(* Logix 5000 project; controller SIKO_example_SN5oEIP_RSL5K_V20 vendor 1 type 14 code 107 rev 20.19; software revision 20.04 *)

TASK MainTask (continuous, watchdog 500 ms) : MainProgram

MODULES
   Local : vendor 1 type 14 code 107 (Compact 0, rev 20.19)
      ABC : ETHERNET-MODULE (Ethernet 10.129.140.221, rev 1.1, Output RPI 10 ms)
END_MODULES

ADD_ON_INSTRUCTION SIKO_AG05_CSW_POS   (* revision 1.0, vendor SIKO GmbH *)
// Control-/Status-Word
VAR_IN_OUT
   DC_Com : SIKO_SN5_COM; {required}
END_VAR
VAR_INPUT
   bc00_Off1 : BOOL; {visible}   // Bit = 1 (Required for movement)
   bc01_Off2 : BOOL; {visible}   // Bit = 1 (Required for movement)
   bc02_Off3 : BOOL; {visible}   // Bit = 1 (Required for movement)
   bc03_IntermediateStop : BOOL; {visible}
   bc04_StartTravelJob : BOOL; {visible}
   bc05_AckError : BOOL; {visible}
   bc06_InchingMode1 : BOOL; {visible}
   bc07_Inching2Pos : BOOL; {visible}
   bc08_Inching2Neg : BOOL; {visible}
   bc09_KeyEnable : BOOL; {visible}
   bcCal : BOOL; {visible}
END_VAR
VAR_OUTPUT
   bs00_Supply : BOOL; {access Read Only, visible}
   bs01_ReadinessToTravel : BOOL; {access Read Only, visible}
   bs02_UpperLimit : BOOL; {access Read Only, visible}
   bs03_LowerLimit : BOOL; {access Read Only, visible}
   bs04_ActuatorTravels : BOOL; {access Read Only, visible}
   bs05_InPos : BOOL; {access Read Only, visible}
   bs06_ActiveTravelJob : BOOL; {access Read Only, visible}
   bs07_Error : BOOL; {access Read Only, visible}
   bs08_OperationEnabled : BOOL; {access Read Only, visible}
   bs09_SwitchLock : BOOL; {access Read Only, visible}
   bs10_TravelJobAck : BOOL; {access Read Only, visible}
   bs11_BatteryWarning : BOOL; {access Read Only, visible}
   bs12_CurrentLimiting : BOOL; {access Read Only, visible}
   bsCalExec : BOOL; {access Read Only, visible}
END_VAR

ROUTINE Logic   (* structured text *)
   ////////////////////////////////////////////////////////////////////////
   // Version history
   ////////////////////////////////////////////////////////////////////////
   // Date       | Vers. | created              | Author          | Remark
   // dd.mm.yyyy |       | with                 |                 |
   // --------------------------------------------------------------------
   // 10.10.2018 | 0.01  | RSLogix5000 V 19.01  | SIKO GmbH / MK  | alpha
   ////////////////////////////////////////////////////////////////////////
   //
   ///////////////////////////////////////////////////////////////////////////////////////////////
   // Control-/ Statusword symbolic
   //
   DC_Com.bc00 	:= bc00_Off1;
   DC_Com.bc01 	:= bc01_Off2;
   DC_Com.bc02 	:= bc02_Off3;
   DC_Com.bc03 	:= bc03_IntermediateStop;
   DC_Com.bc04 	:= bc04_StartTravelJob;
   DC_Com.bc05 	:= bc05_AckError;
   DC_Com.bc06 	:= bc06_InchingMode1;
   DC_Com.bc07 	:= bc07_Inching2Pos;
   DC_Com.bc08 	:= bc08_Inching2Neg;
   DC_Com.bc09 	:= bc09_KeyEnable;
   DC_Com.bc10 	:= 0;
   DC_Com.bc11 	:= 0;
   DC_Com.bc12 	:= 0;
   DC_Com.bc13 	:= 0;
   DC_Com.bc14 	:= 0;
   DC_Com.bc15 	:= 0;
   DC_Com.bcCal 	:= bcCal;
   
   bs00_Supply 			:= DC_Com.bs00;
   bs01_ReadinessToTravel 	:= DC_Com.bs01;
   bs02_UpperLimit 		:= DC_Com.bs02;
   bs03_LowerLimit 		:= DC_Com.bs03;
   bs04_ActuatorTravels 	:= DC_Com.bs04;
   bs05_InPos 				:= DC_Com.bs05;
   bs06_ActiveTravelJob 	:= DC_Com.bs06;
   bs07_Error				:= DC_Com.bs07;
   bs08_OperationEnabled 	:= DC_Com.bs08;
   bs09_SwitchLock 		:= DC_Com.bs09;
   bs10_TravelJobAck 		:= DC_Com.bs10;
   bs11_BatteryWarning 	:= DC_Com.bs11;
   bs12_CurrentLimiting	:= DC_Com.bs12;
   bsCalExec 				:= DC_Com.bsCalExec;
   
   
   
   
   
   
   
END_ROUTINE
END_ADD_ON_INSTRUCTION

ADD_ON_INSTRUCTION SIKO_AP10   (* revision 5.0 4, vendor SIKO GmbH *)
// SIKO PositionLine AP10 AOI
// Revision note:
// Usable with AP10 Firmware Vers. >= 1.06
VAR_IN_OUT
   DC_OutputBuffer : SINT[10]; {required}
   DC_AbcOutputRegister : AB:ETHERNET_MODULE_SINT_314Bytes:O:0; {required}
END_VAR
VAR_INPUT
   DC_AbcStartByteOut : INT; {required}
END_VAR
VAR_IN_OUT
   DC_InputBuffer : SINT[10]; {required}
   DC_AbcInputRegister : AB:ETHERNET_MODULE_SINT_314Bytes:I:0; {required}
END_VAR
VAR_INPUT
   DC_AbcStartByteIn : INT; {required}
   nNodeId : SINT; {visible}   // Temporaray Node_address
   nSetValue : DINT; {visible}
END_VAR
VAR_OUTPUT
   nActualValue : DINT; {access Read Only, visible}
END_VAR
VAR_INPUT
   nParameterAdrRead1 : SINT; {visible}
   nParameterAdrRead2 : SINT; {visible}
   nParameterAdrRead3 : SINT; {visible}
   bcStartRead : BOOL; {visible}
   bcStartWrite : BOOL; {visible}
   bcStartCopy : BOOL; {visible}
   bcResetCounterActivity : BOOL; {visible}
END_VAR
VAR_OUTPUT
   nCounterRead : INT; {access Read Only, visible}
   nCounterWrite : INT; {access Read Only, visible}
   nCounterCopy : INT; {access Read Only, visible}
   nErrorCode1 : SINT; {access Read Only, visible}
   nErrorCode2 : SINT; {access Read Only, visible}
   p00_NodeAddress_r : SINT; {access Read Only, visible}   // Parmeter: 0x00
END_VAR
VAR_INPUT
   p00_NodeAddress_w : SINT := 31; {visible}   // Parmeter: 0x00
END_VAR
VAR_OUTPUT
   p01_Baudrate_r : SINT; {access Read Only}   // Parmeter: 0x01
END_VAR
VAR_INPUT
   p01_Baudrate_w : SINT := 1;   // Parmeter: 0x01
END_VAR
VAR_OUTPUT
   p02_BusTimeout_r : SINT; {access Read Only}   // Parmeter: 0x02
END_VAR
VAR_INPUT
   p02_BusTimeout_w : SINT := 20;   // Parmeter: 0x02
END_VAR
VAR_OUTPUT
   p03_ReplyWriteSetPoint_r : SINT;   // Parmeter: 0x03
END_VAR
VAR_INPUT
   p03_ReplyWriteSetPoint_w : SINT; {access Read Only}   // Parmeter: 0x03
END_VAR
VAR_OUTPUT
   p04_EnableKeysTime_r : SINT; {access Read Only}   // Parmeter: 0x04
END_VAR
VAR_INPUT
   p04_EnableKeysTime_w : SINT := 5;   // Parmeter: 0x04
END_VAR
VAR_OUTPUT
   p05_KeyFunctionEnable1Calibrate_r : SINT; {access Read Only}   // Parmeter: 0x05
END_VAR
VAR_INPUT
   p05_KeyFunctionEnable1Calibrate_w : SINT := 1;   // Parmeter: 0x05
END_VAR
VAR_OUTPUT
   p06_LedFlashing_r : SINT; {access Read Only}   // Parmeter: 0x06
END_VAR
VAR_INPUT
   p06_LedFlashing_w : SINT;   // Parmeter: 0x06
END_VAR
VAR_OUTPUT
   p07_Led3Green_r : SINT; {access Read Only}   // Parmeter: 0x07
END_VAR
VAR_INPUT
   p07_Led3Green_w : SINT := 1;   // Parmeter: 0x07
END_VAR
VAR_OUTPUT
   p08_Led2Red_r : SINT; {access Read Only}   // Parmeter: 0x08
END_VAR
VAR_INPUT
   p08_Led2Red_w : SINT := 1;   // Parmeter: 0x08
END_VAR
VAR_OUTPUT
   p09_Led1Green_r : SINT; {access Read Only}   // Parmeter: 0x09
END_VAR
VAR_INPUT
   p09_Led1Green_w : SINT := 1;   // Parmeter: 0x09
END_VAR
VAR_OUTPUT
   p0A_DecimalPlaces_r : SINT; {access Read Only}   // Parmeter: 0x0A
END_VAR
VAR_INPUT
   p0A_DecimalPlaces_w : SINT;   // Parmeter: 0x0A
END_VAR
VAR_OUTPUT
   p0B_DisplayDivisor_r : SINT; {access Read Only}   // Parmeter: 0x0B
END_VAR
VAR_INPUT
   p0B_DisplayDivisor_w : SINT;   // Parmeter: 0x0B
END_VAR
VAR_OUTPUT
   p0C_DirectionIndication_r : SINT; {access Read Only}   // Parmeter: 0x0C
END_VAR
VAR_INPUT
   p0C_DirectionIndication_w : SINT := 1;   // Parmeter: 0x0C
END_VAR
VAR_OUTPUT
   p0D_DisplayOrientation_r : SINT; {access Read Only}   // Parmeter: 0x0D
END_VAR
VAR_INPUT
   p0D_DisplayOrientation_w : SINT;   // Parmeter: 0x0D
END_VAR
VAR_OUTPUT
   p0E_ProgrammingMode_r : SINT; {access Read Only}   // Parmeter: 0x0E
END_VAR
VAR_INPUT
   p0E_ProgrammingMode_w : SINT; {access Read Only}   // Parmeter: 0x0E
END_VAR
VAR_OUTPUT
   p1B_CountingDirection_r : SINT; {access Read Only}   // Parmeter: 0x1B
END_VAR
VAR_INPUT
   p1B_CountingDirection_w : SINT;   // Parmeter: 0x1B
END_VAR
VAR_OUTPUT
   p1C_ResolutionPerRevolution_r : DINT; {access Read Only}   // Parmeter: 0x1C
END_VAR
VAR_INPUT
   p1C_ResolutionPerRevolution_w : DINT := 880;   // Parmeter: 0x1C
END_VAR
VAR_OUTPUT
   p1E_Offset_r : INT; {access Read Only}   // Parmeter: 0x1E
END_VAR
VAR_INPUT
   p1E_Offset_w : INT;   // Parmeter: 0x1E
END_VAR
VAR_OUTPUT
   p1F_CalibrationValue_r : DINT; {access Read Only}   // Parmeter: 0x1F
END_VAR
VAR_INPUT
   p1F_CalibrationValue_w : DINT;   // Parmeter: 0x1F
END_VAR
VAR_OUTPUT
   p20_TargetWindow1_r : INT; {access Read Only}   // Parmeter: 0x20
END_VAR
VAR_INPUT
   p20_TargetWindow1_w : INT;   // Parmeter: 0x20
END_VAR
VAR_OUTPUT
   p21_PosType_r : SINT; {access Read Only}   // Parmeter: 0x21
END_VAR
VAR_INPUT
   p21_PosType_w : SINT;   // Parmeter: 0x21
END_VAR
VAR_OUTPUT
   p22_LoopLength_r : INT; {access Read Only}   // Parmeter: 0x22
END_VAR
VAR_INPUT
   p22_LoopLength_w : INT;   // Parmeter: 0x22
END_VAR
VAR_OUTPUT
   p28_OperatingMode_r : SINT; {access Read Only}   // Parmeter: 0x28
END_VAR
VAR_INPUT
   p28_OperatingMode_w : SINT;   // Parmeter: 0x28
END_VAR
VAR_OUTPUT
   p30_Display2Line_r : SINT; {access Read Only}   // Parmeter: 0x30
END_VAR
VAR_INPUT
   p30_Display2Line_w : SINT := 1;   // Parmeter: 0x30
END_VAR
VAR_OUTPUT
   p31_TargetWindow2_r : INT; {access Read Only}   // Parmeter: 0x31
END_VAR
VAR_INPUT
   p31_TargetWindow2_w : INT;   // Parmeter: 0x31
   p32_PosWindow2Visual_w : SINT;   // Parmeter: 0x32
END_VAR
VAR_OUTPUT
   p32_PosWindow2Visual_r : SINT; {access Read Only}   // Parmeter: 0x32
   p33_DisplayDivisorUse_r : SINT; {access Read Only}   // Parmeter: 0x33
END_VAR
VAR_INPUT
   p33_DisplayDivisorUse_w : SINT;   // Parmeter: 0x33
   p34_DifferenceValueCalc_w : SINT;   // Parmeter: 0x34
END_VAR
VAR_OUTPUT
   p34_DifferenceValueCalc_r : SINT; {access Read Only}   // Parmeter: 0x34
   p35_KeyFunctionEnable2IncrMeas_r : SINT; {access Read Only}   // Parmeter: 0x35
END_VAR
VAR_INPUT
   p35_KeyFunctionEnable2IncrMeas_w : SINT := 1;   // Parmeter: 0x35
END_VAR
VAR_OUTPUT
   p39_Led4Red_r : SINT; {access Read Only}   // Parmeter: 0x39
END_VAR
VAR_INPUT
   p39_Led4Red_w : SINT := 1;   // Parmeter: 0x39
END_VAR
VAR_OUTPUT
   p3A_LcdBacklightFlashing_r : SINT; {access Read Only}   // Parmeter: 0x3A
END_VAR
VAR_INPUT
   p3A_LcdBacklightFlashing_w : SINT;   // Parmeter: 0x3A
END_VAR
VAR_OUTPUT
   p3B_LcdBacklightWhite_r : SINT; {access Read Only}   // Parmeter: 0x3B
END_VAR
VAR_INPUT
   p3B_LcdBacklightWhite_w : SINT := 1;   // Parmeter: 0x3B
END_VAR
VAR_OUTPUT
   p3C_LcdBacklightRed_r : SINT; {access Read Only}   // Parmeter: 0x3C
END_VAR
VAR_INPUT
   p3C_LcdBacklightRed_w : SINT := 1;   // Parmeter: 0x3C
END_VAR
VAR_OUTPUT
   p3D_KeyFunctionEnable3Config_r : SINT; {access Read Only}   // Parmeter: 0x3D
END_VAR
VAR_INPUT
   p3D_KeyFunctionEnable3Config_w : SINT := 1;   // Parmeter: 0x3D
END_VAR
VAR_OUTPUT
   p3E_AcknowledgementSettings_r : SINT; {access Read Only}   // Parmeter: 0x3E
END_VAR
VAR_INPUT
   p3E_AcknowledgementSettings_w : SINT;   // Parmeter: 0x3E
END_VAR
VAR_OUTPUT
   p3F_IndicationFactor_r : SINT; {access Read Only}   // Parmeter: 0x3F
END_VAR
VAR_INPUT
   p3F_IndicationFactor_w : SINT;   // Parmeter: 0x3F
END_VAR
VAR_OUTPUT
   p63_VoltageBattery_r : INT; {access Read Only}   // Parmeter: 0x63
   p65_DeviceCode_r : INT; {access Read Only}   // Parmeter: 0x65
   p67_SoftwareVersion_r : INT; {access Read Only}   // Parmeter: 0x67
   p80_NumberOfErrorsRecorded_r : SINT; {access Read Only}   // Parmeter: 0x80
   p81_Error01_r : SINT; {access Read Only}   // Parmeter: 0x81
   p82_Error02_r : SINT; {access Read Only}   // Parmeter: 0x82
   p83_Error03_r : SINT; {access Read Only}   // Parmeter: 0x83
   p84_Error04_r : SINT; {access Read Only}   // Parmeter: 0x84
   p85_Error05_r : SINT; {access Read Only}   // Parmeter: 0x85
   p86_Error06_r : SINT; {access Read Only}   // Parmeter: 0x86
   p87_Error07_r : SINT; {access Read Only}   // Parmeter: 0x87
   p88_Error08_r : SINT; {access Read Only}   // Parmeter: 0x88
   p89_Error09_r : SINT; {access Read Only}   // Parmeter: 0x89
   p8A_Error10_r : SINT; {access Read Only}   // Parmeter: 0x8A
   p96_InputErrors_r : INT; {access Read Only}   // Parmeter: 0x96
END_VAR
VAR_INPUT
   pA0_SystemCommand_w : SINT;   // Parmeter: 0xA0
   pA7_ExecuteCalibration_w : SINT;   // Parmeter: 0xA7
END_VAR
VAR_OUTPUT
   pA8_ProgrammingModeOnOff_r : SINT; {access Read Only}   // Parmeter: 0xA8
END_VAR
VAR_INPUT
   pA8_ProgrammingModeOnOff_w : SINT;   // Parmeter: 0xA8
   pAA_FreezeAV_w : SINT;   // Parmeter: 0xAA
END_VAR
VAR_OUTPUT
   pC5_AdcValuesSensor_r : DINT;   // Parmeter: 0xC5
   pCF_PeriodCounter_r : DINT;   // Parmeter: 0xCF
   pD0_ResponseDelay_r : SINT; {access Read Only}   // Parmeter: 0xD0
END_VAR
VAR_INPUT
   pD0_ResponseDelay_w : SINT;   // Parmeter: 0xD0
   pD2_AutoIdAssignment_w : SINT;   // Parmeter: 0xD2
END_VAR
VAR_OUTPUT
   pFA_SystemStatusword_r : INT; {access Read Only}   // Parmeter: 0xFA
   pFB_SetPoint1_r : DINT; {access Read Only}   // Parmeter: 0xFB
END_VAR
VAR_INPUT
   pFB_SetPoint1_w : DINT;   // Parmeter: 0xFB
END_VAR
VAR_OUTPUT
   pFC_DifferentialValue_r : DINT; {access Read Only}   // Parmeter: 0xFC
   pFE_ActualPosition_r : DINT; {access Read Only}   // Parmeter: 0xFE
   pFF_SetPoint2_r : DINT; {access Read Only}   // Parmeter: 0xFF
END_VAR
VAR_INPUT
   pFF_SetPoint2_w : DINT;   // Parmeter: 0xFF
   bc02_ValidityOfSetpoint1 : BOOL;
   bc03_DisplayRange : BOOL;
   bc04_AcknowledgmentTargetWindow1Static : BOOL;
   bc05_ErrorAcknowledgment : BOOL;
   bc06_AcknowledgementOfSetpoint2 : BOOL;
   bc07_DataIdentifier : BOOL;
   bc09_ValidityOfSetpoint2 : BOOL;
   bc10_AcknowledgementOfSetpoint1 : BOOL;
   bc11_Led1GreenLeft : BOOL;
   bc12_Led3GreenRight : BOOL;
   bc13_Led4RedRight : BOOL;
   bc14_Led2RedLeft : BOOL;
   bc15_LedBlinking : BOOL;
END_VAR
VAR_OUTPUT
   bs00_DirectionIndicationCw : BOOL; {access Read Only}
   bs01_DirectionIndicationCcw : BOOL; {access Read Only}
   bs02_ValiditySetpoint1 : BOOL; {access Read Only}
   bs03_TargetWindow2Dynamic : BOOL; {access Read Only}
   bs04_TargetWindow1Static : BOOL; {access Read Only}
   bs05_TargetWindow1Dynamic : BOOL; {access Read Only}
   bs06_Deviation : BOOL; {access Read Only}
   bs07_DeviceError : BOOL; {access Read Only}
   bs08_OutputOfPositionValue : BOOL; {access Read Only}
   bs09_PositionValueIncrementalMeasurement : BOOL; {access Read Only}
   bs10_ValiditySetpoint2 : BOOL;
   bs11_BatteryStatus : BOOL; {access Read Only}
   bs12_SensorError : BOOL;
   bs13_ButtonLeft : BOOL; {access Read Only}
   bs14_ButtonStar : BOOL; {access Read Only}
   bs15_ButtonUp : BOOL; {access Read Only}
   bsDone : BOOL; {access Read Only, visible}
   bsBusy : BOOL; {access Read Only, visible}
   bsGeneralError : BOOL; {access Read Only, visible}
   bsFaultDataRecive : BOOL; {access Read Only, visible}
END_VAR
VAR
   vnTrigger : SINT; {access None}
   vnCounterToggle : SINT; {access None}
   vnParameterAdrReceive : INT; {access None}
   vnParameterAdrSend : INT; {access None}
   vnParameterDataReceive : DINT; {access None}
   vnParameterDataSend : DINT; {access None}
   vbRefresh : BOOL; {access None}
   vbOsrWrite : BOOL; {access None}
   vbOsrRead : BOOL; {access None}
   vnOutputDataOffset : DINT := -200; {access None}
   vnDcOutputBufferTemp : DINT; {access None}
   vnDcInputBufferTemp : DINT; {access None}
   vbOsrCopy : BOOL; {access None}
END_VAR

ROUTINE Logic   (* structured text *)
   ///////////////////////////////////////////////////////////////////////////////////////////////
   // Name:	SIKO_AP10
   ///////////////////////////////////////////////////////////////////////////////////////////////
   // Version history
   ///////////////////////////////////////////////////////////////////////////////////////////////
   // Date        | Version  | created under          	| Author    		| Remark
   // dd.mm.yyyy  | 		  |							|					|
   // -----------------------------------------------------------------------------------
   // 26.05.2015  | 4.9.0    | V19.01.00 (CPR 9 SR 3)  | SIKO GmbH / SC 	| basic version
   // 07.09.2015  | 5.0.1    | V19.01.00 (CPR 9 SR 3)  | SIKO GmbH / SC 	| Release Candidate
   ///////////////////////////////////////////////////////////////////////////////////////////////
   
   ///////////////////////////////////////////////////////////////////////////////////////////////
   // read inputs synchonous
   //
   CPS(DC_AbcInputRegister.data[DC_AbcStartByteIn] , DC_InputBuffer[0],10); // read from ABC
   
   ///////////////////////////////////////////////////////////////////////////////////////////////
   // input byte swop to parameter data and format transfer vnParameterAdrReceive
   //
   cop (DC_InputBuffer[5], vnDcInputBufferTemp, 1);					//Data Type Conversion
   swpb (vnDcInputBufferTemp, Reverse, vnParameterDataReceive);
   
   vnParameterAdrReceive := 16#00ff and DC_InputBuffer[2];
   
   ///////////////////////////////////////////////////////////////////////////////////////////////
   // Telegram acknowledge checked for bad reply
   //
   if vnParameterAdrReceive = 253
   then
   	bsFaultDataRecive := 1;
   	nErrorCode1 := DC_InputBuffer[8];
   	nErrorCode2 := DC_InputBuffer[7];
   
   else
   	bsFaultDataRecive := 0;
   	nErrorCode1 := 0;
   	nErrorCode2 := 0;
   end_if;
   
   
   ///////////////////////////////////////////////////////////////////////////////////////////////
   // Request (Read/Write) successful
   //
   if DC_OutputBuffer[2] = DC_InputBuffer[2] and not bsFaultDataRecive
   then
   	if nCounterRead <> 0
   	then
   		nCounterRead := nCounterRead + 1;
   	end_if;
   	if nCounterWrite <> 0
   	then
   		nCounterWrite := nCounterWrite + 1;
   	end_if;
   end_if;
   
   ///////////////////////////////////////////////////////////////////////////////////////////////
   // Control word
   //
   DC_OutputBuffer[4].0 := 0;
   DC_OutputBuffer[4].1 := 0;
   DC_OutputBuffer[4].2 := bc02_ValidityOfSetpoint1;                // Validity of setpoint1; 0=invalid; 1=valid
   DC_OutputBuffer[4].3 := bc03_DisplayRange;                       // Display range full
   DC_OutputBuffer[4].4 := bc04_AcknowledgmentTargetWindow1Static;  // Acknowledgment target window1 static
   DC_OutputBuffer[4].5 := bc05_ErrorAcknowledgment;                // Acknowledged
   DC_OutputBuffer[4].6 := bc06_AcknowledgementOfSetpoint2;         // Acknowledgment Set Value2
   DC_OutputBuffer[4].7 := bc07_DataIdentifier;                     // Data format, Number / ASCII-String
   DC_OutputBuffer[3].0 := 0;
   DC_OutputBuffer[3].1 := bc09_ValidityOfSetpoint2;                // Validity of setpoint2
   DC_OutputBuffer[3].2 := bc10_AcknowledgementOfSetpoint1;         // Acknowledgment Set Value2
   DC_OutputBuffer[3].3 := bc11_Led1GreenLeft;                      // LED1 green left
   DC_OutputBuffer[3].4 := bc12_Led3GreenRight;                     // LED3 green right
   DC_OutputBuffer[3].5 := bc13_Led4RedRight;                       // LED4 red right
   DC_OutputBuffer[3].6 := bc14_Led2RedLeft;                        // LED2 red left
   DC_OutputBuffer[3].7 := bc15_LedBlinking;                        // LED blinking
   
   ///////////////////////////////////////////////////////////////////////////////////////////////
   // Start Read
   //
   IF bcStartRead AND (nCounterRead = 0) AND (nCounterWrite = 0) AND (nCounterCopy = 0) AND NOT vbOsrRead
   THEN
   	nCounterRead := 1;
   	nCounterWrite := 0;
   	nCounterCopy := 0;
   	vbOsrRead := 1;
   END_IF;
   IF NOT bcStartRead and vbOsrRead
   THEN
   	vbOsrRead := 0;
   END_IF;
   
   ///////////////////////////////////////////////////////////////////////////////////////////////
   // Start Write
   //
   IF bcStartWrite AND (nCounterRead = 0) AND (nCounterWrite = 0) AND (nCounterCopy = 0) AND NOT vbOsrWrite
   THEN
   	nCounterWrite := 1;
   	nCounterRead := 0;
   	nCounterCopy := 0;
   	vbOsrWrite := 1;
   END_IF;
   IF NOT bcStartWrite and vbOsrWrite
   THEN
   	vbOsrWrite := 0;
   END_IF;
   
   ///////////////////////////////////////////////////////////////////////////////////////////////
   // copy read to write parameters
   //
   IF bcStartCopy AND (nCounterRead = 0) AND (nCounterWrite = 0) AND (nCounterCopy = 0) AND NOT vbOsrCopy
   THEN
   	nCounterCopy := 1;
   	nCounterWrite := 0;
   	nCounterRead := 0;
   	vbOsrCopy := 1;
   END_IF;
   IF NOT bcStartCopy and vbOsrCopy
   THEN
   	vbOsrCopy := 0;
   END_IF;
   
   ///////////////////////////////////////////////////////////////////////////////////////////////
   // reset counter (nCounter...) and activity (bcStart...)
   //
   IF bcResetCounterActivity
   THEN
   	bcStartRead :=0;
   	bcStartWrite :=0;
   	bcStartCopy :=0;
   	nCounterCopy := 0;
   	nCounterWrite := 0;
   	nCounterRead := 0;
   	vnCounterToggle := 0;
   	bcResetCounterActivity := 0;
   END_IF;
   
   ///////////////////////////////////////////////////////////////////////////////////////////////
   // Parameter request
   //
   if nCounterRead > 0
   	then
   	DC_OutputBuffer[0] := 0;
   	vnParameterDataSend := 0;
   	CASE nCounterRead OF
   	1: //0x00 Note address
   	    vnParameterAdrSend := 0;
   	2: //0x01 Baud rate
   		vnParameterAdrSend := 1;
   	3: //0x02 Bus Timeout
         	vnParameterAdrSend := 2;
   	4: //0x03 Response parameter to a setpoint write access
         	vnParameterAdrSend := 3;
   	5: //0x04 Keys enable time: Configuration start delay
         	vnParameterAdrSend := 4;
   	6: //0x05 Key function enable1: Calibration enable
         	vnParameterAdrSend := 5;
   	7: //0x06 LED flashing
         	vnParameterAdrSend := 6;
   	8: //0x07 LED3 (green right)
         	vnParameterAdrSend := 7;
   	9: //0x08 LED2 (red left)
         	vnParameterAdrSend := 8;
   	10: //0x09 LED1 (green left)
         	vnParameterAdrSend := 9;
   	11: //0x0A Decimal places
         	vnParameterAdrSend := 10;
   	12: //0x0B Display divisor (ADI)
         	vnParameterAdrSend := 11;
   	13: //0x0C Direction indicators (CW, CCW)
         	vnParameterAdrSend := 12;
   	14: //0x0D Display orientation
         	vnParameterAdrSend := 13;
   	15: //0x0E Configuration programming mode
         	vnParameterAdrSend := 14;
   	16: //0x1B Counting direction
         	vnParameterAdrSend := 27;
   	17: //0x1C Resolution per revolution
         	vnParameterAdrSend := 28;
   	18: //0x1E Offset value
         	vnParameterAdrSend := 30;
   	19: //0x1F Calibration value
         	vnParameterAdrSend := 31;
   	20: //0x20 Target window1 (near field)
         	vnParameterAdrSend := 32;
   	21: //0x21 Positioning type (loop type)
         	vnParameterAdrSend := 33;
   	22: //0x22 Loop length
         	vnParameterAdrSend := 34;
   	23: //0x28 Operating mode
         	vnParameterAdrSend := 40;
   	24: //0x30 Display in the 2nd row
         	vnParameterAdrSend := 48;
   	25: //0x31 Target window2 (extended)
         	vnParameterAdrSend := 49;
   	26: //0x32 Target window2 visualization
         	vnParameterAdrSend := 50;
   	27: //0x33 Application of the display divisor (ADI application)
         	vnParameterAdrSend := 51;
   	28: //0x34 Formation of the differential value
         	vnParameterAdrSend := 52;
   	29: //0x35 Key function enable2: Incremental measurement enable
         	vnParameterAdrSend := 53;
   	30: //0x39 LED4 (red right)
         	vnParameterAdrSend := 57;
   	31: //0x3A LCD backlight flashing
         	vnParameterAdrSend := 58;
   	32: //0x3B LCD backlight white
         	vnParameterAdrSend := 59;
   	33: //0x3C LCD backlight red
         	vnParameterAdrSend := 60;
   	34: //0x3D Key function enable3: Configuration enable via keyboard
         	vnParameterAdrSend := 61;
   	35: //0x3E Acknowledgement settings
         	vnParameterAdrSend := 62;
   	36: //0x3F Indication factor
   		//vnParameterAdrSend := 63;
   	37: //0x63 Battery voltage
         	vnParameterAdrSend := 99;
   	38: //0x65 Device identification
         	vnParameterAdrSend := 101;
   	39: //0x67 Software version
         	vnParameterAdrSend := 103;
   	40: //0x80 Number of errors
         	vnParameterAdrSend := 128;
   	41: //0x81 Error 01
         	vnParameterAdrSend := 129;
   	42: //0x82 Error 02
         	vnParameterAdrSend := 130;
   	43: //0x83 Error 03
         	vnParameterAdrSend := 131;
   	44: //0x84 Error 04
         	vnParameterAdrSend := 132;
   	45: //0x85 Error 05
         	vnParameterAdrSend := 133;
   	46: //0x86 Error 06
         	vnParameterAdrSend := 134;
   	47: //0x87 Error 07
         	vnParameterAdrSend := 135;
   	48: //0x88 Error 08
         	vnParameterAdrSend := 136;
   	49: //0x89 Error 09
         	vnParameterAdrSend := 137;
   	50: //0x8A Error 10
         	vnParameterAdrSend := 138;
   	51: //0x96 Input Errors
   		//vnParameterAdrSend := 150;
   	52: //0xC5 ADC values of the sensor
         	vnParameterAdrSend := 197;
   	53: //0xCF Period counter
         	vnParameterAdrSend := 207;
   	54: //0xD0 Response delay
         	vnParameterAdrSend := 208;
   	55: //0xFA System Status word
         	vnParameterAdrSend := 250;
   	56: //0xFB Setpoint1
         	vnParameterAdrSend := 251;
   	57: //0xFC Differential value
         	vnParameterAdrSend := 252;
   	58: //0xFE Position value
         	vnParameterAdrSend := 254;
   	59: //0xFF Setpoint2
         	vnParameterAdrSend := 255;
   	60: // Parameter anforderung abgeschlossen
   		nCounterRead := 0;
     	END_CASE;
   end_if;
   
   ///////////////////////////////////////////////////////////////////////////////////////////////
   // Parameter Settings
   //
   if nCounterWrite > 0
   	then
   	DC_OutputBuffer[0] := 1;
   	CASE nCounterWrite OF
   	1: //Programming mode
   		IF pA8_ProgrammingModeOnOff_w >= 0 and pA8_ProgrammingModeOnOff_w <= 1
   		THEN
   	      	vnParameterAdrSend := 168;
   			vnParameterDataSend:= pA8_ProgrammingModeOnOff_w;
   		END_IF;
   	2: //Note address
   		IF p00_NodeAddress_w <> p00_NodeAddress_r or bsFaultDataRecive
   		THEN
   	      	vnParameterAdrSend := 0;
   			vnParameterDataSend:= p00_NodeAddress_w;
   		END_IF;
   	3: //Baudrate
   		IF p01_Baudrate_w <> p01_Baudrate_r or bsFaultDataRecive
   		THEN
   	      	vnParameterAdrSend := 1;
   			vnParameterDataSend:= p01_Baudrate_w;
   		END_IF;
   	4: //Bus Timeout
   		IF p02_BusTimeout_w <> p02_BusTimeout_r or bsFaultDataRecive
   		THEN
   	      	vnParameterAdrSend := 2;
   			vnParameterDataSend:= p02_BusTimeout_w;
   		END_IF;
   	5: //Response parameter to a setpoint write access
   		IF p03_ReplyWriteSetPoint_w <> p03_ReplyWriteSetPoint_r or bsFaultDataRecive
   		THEN
   	      	vnParameterAdrSend := 3;
   			vnParameterDataSend:= p03_ReplyWriteSetPoint_w;
   		END_IF;
   	6: ///Keys enable time: Configuration start delay
   		IF p04_EnableKeysTime_w <> p04_EnableKeysTime_r or bsFaultDataRecive
   		THEN
   	      	vnParameterAdrSend := 4;
   			vnParameterDataSend:= p04_EnableKeysTime_w;
   		END_IF;
   	7: //Key function enable1: Calibration enable
   		IF p05_KeyFunctionEnable1Calibrate_w <> p05_KeyFunctionEnable1Calibrate_r or bsFaultDataRecive
   		THEN
   	      	vnParameterAdrSend := 5;
   			vnParameterDataSend:= p05_KeyFunctionEnable1Calibrate_w;
   		END_IF;
   	8: //LED flashing
   		IF p06_LedFlashing_w <> p06_LedFlashing_r or bsFaultDataRecive
   		THEN
   	      	vnParameterAdrSend := 6;
   			vnParameterDataSend:= p06_LedFlashing_w;
   		END_IF;
   	9: //LED3 (green right)
   		IF p07_Led3Green_w <> p07_Led3Green_r or bsFaultDataRecive
   		THEN
   	      	vnParameterAdrSend := 7;
   			vnParameterDataSend:= p07_Led3Green_w;
   		END_IF;
   	10: //LED2 (red left)
   		IF p08_Led2Red_w <> p08_Led2Red_r or bsFaultDataRecive
   		THEN
   	      	vnParameterAdrSend := 8;
   			vnParameterDataSend:= p08_Led2Red_w;
   		END_IF;
   	11: //LED1 (green left)
   		IF p09_Led1Green_w <> p09_Led1Green_r or bsFaultDataRecive
   		THEN
   	      	vnParameterAdrSend := 9;
   			vnParameterDataSend:= p09_Led1Green_w;
   		END_IF;
   	12: //Decimal places
   		IF p0A_DecimalPlaces_w <> p0A_DecimalPlaces_r or bsFaultDataRecive
   		THEN
   	      	vnParameterAdrSend := 10;
   			vnParameterDataSend := p0A_DecimalPlaces_w;
   		END_IF;
   	13: //Display divisor (ADI)
   		IF p0B_DisplayDivisor_w <> p0B_DisplayDivisor_r or bsFaultDataRecive
   		THEN
   	      	vnParameterAdrSend := 11;
   			vnParameterDataSend:= p0B_DisplayDivisor_w;
   		END_IF;
   	14: //Direction indicators (CW, CCW)
   		IF p0C_DirectionIndication_w <> p0C_DirectionIndication_r or bsFaultDataRecive
   		THEN
   	      	vnParameterAdrSend := 12;
   			vnParameterDataSend:= p0C_DirectionIndication_w;
   		END_IF;
   	15: //Display orientation
   		IF p0D_DisplayOrientation_w <> p0D_DisplayOrientation_r or bsFaultDataRecive
   		THEN
   	      	vnParameterAdrSend := 13;
   			vnParameterDataSend:= p0D_DisplayOrientation_w;
   		END_IF;
   	16: //Configuration programming mode
   		IF p0E_ProgrammingMode_w <> p0E_ProgrammingMode_r or bsFaultDataRecive
   		THEN
   	      	vnParameterAdrSend := 14;
   			vnParameterDataSend:= p0E_ProgrammingMode_w;
   		END_IF;
   	17: //Counting direction
   		IF p1B_CountingDirection_w <> p1B_CountingDirection_r or bsFaultDataRecive
   		THEN
   	      	vnParameterAdrSend := 27;
   			vnParameterDataSend:= p1B_CountingDirection_w;
   		END_IF;
   	18: //Resolution per revolution
   		IF p1C_ResolutionPerRevolution_w <> p1C_ResolutionPerRevolution_r or bsFaultDataRecive
   		THEN
   	      	vnParameterAdrSend := 28;
   			vnParameterDataSend:= p1C_ResolutionPerRevolution_w;
   		END_IF;
   	19: //Offset value
   		IF p1E_Offset_w <> p1E_Offset_r or bsFaultDataRecive
   		THEN
   	      	vnParameterAdrSend := 30;
   			vnParameterDataSend:= p1E_Offset_w;
   		END_IF;
   	20: //Calibration value
   		IF p1F_CalibrationValue_w <> p1F_CalibrationValue_r or bsFaultDataRecive
   		THEN
   	      	vnParameterAdrSend := 31;
   			vnParameterDataSend:= p1F_CalibrationValue_w;
   		END_IF;
   	21: //Target window1 (near field)
   		IF p20_TargetWindow1_w <> p20_TargetWindow1_r or bsFaultDataRecive
   		THEN
   	      	vnParameterAdrSend := 32;
   			vnParameterDataSend:= p20_TargetWindow1_w;
   		END_IF;
   	22: //Positioning type (loop type)
   		IF p21_PosType_w <> p21_PosType_r or bsFaultDataRecive
   		THEN
   	      	vnParameterAdrSend := 33;
   			vnParameterDataSend:= p21_PosType_w;
   		END_IF;
   	23: //Loop length
   		IF p22_LoopLength_w <> p22_LoopLength_r or bsFaultDataRecive
   		THEN
   	      	vnParameterAdrSend := 34;
   			vnParameterDataSend:= p22_LoopLength_w;
   		END_IF;
   	24: //Operating mode
   		IF p28_OperatingMode_w <> p28_OperatingMode_r or bsFaultDataRecive
   		THEN
   	      	vnParameterAdrSend := 40;
   			vnParameterDataSend:= p28_OperatingMode_w;
   		END_IF;
   	25: //Display in the 2nd row
   		IF p30_Display2Line_w <> p30_Display2Line_r or bsFaultDataRecive
   		THEN
   	      	vnParameterAdrSend := 48;
   			vnParameterDataSend:= p30_Display2Line_w;
   		END_IF;
   	26: //Target window2 (extended)
   		IF p31_TargetWindow2_w <> p31_TargetWindow2_r or bsFaultDataRecive
   		THEN
   	      	vnParameterAdrSend := 49;
   			vnParameterDataSend:= p31_TargetWindow2_w;
   		END_IF;
   	27: //Target window2 visualization
   		IF p32_PosWindow2Visual_w <> p32_PosWindow2Visual_r or bsFaultDataRecive
   		THEN
   	      	vnParameterAdrSend := 50;
   			vnParameterDataSend:= p32_PosWindow2Visual_w;
   		END_IF;
   	28: //Application of the display divisor (ADI application)
   		IF p33_DisplayDivisorUse_w <> p33_DisplayDivisorUse_r or bsFaultDataRecive
   		THEN
   	      	vnParameterAdrSend := 51;
   			vnParameterDataSend:= p33_DisplayDivisorUse_w;
   		END_IF;
   	29: //Formation of the differential value
   		IF p34_DifferenceValueCalc_w <> p34_DifferenceValueCalc_r or bsFaultDataRecive
   		THEN
   	      	vnParameterAdrSend := 52;
   			vnParameterDataSend:= p34_DifferenceValueCalc_w;
   		END_IF;
   	30: //Key function enable2: Incremental measurement enable
   		IF p35_KeyFunctionEnable2IncrMeas_w <> p35_KeyFunctionEnable2IncrMeas_r or bsFaultDataRecive
   		THEN
   	      	vnParameterAdrSend := 53;
   			vnParameterDataSend:= p35_KeyFunctionEnable2IncrMeas_w;
   		END_IF;
   	31: //LED4 (red right)
   		IF p39_Led4Red_w <> p39_Led4Red_r or bsFaultDataRecive
   		THEN
   	      	vnParameterAdrSend := 57;
   			vnParameterDataSend:= p39_Led4Red_w;
   		END_IF;
   	32: //LCD backlight flashing
   		IF p3A_LcdBacklightFlashing_w <> p3A_LcdBacklightFlashing_r or bsFaultDataRecive
   		THEN
   	      	vnParameterAdrSend := 58;
   			vnParameterDataSend:= p3A_LcdBacklightFlashing_w;
   		END_IF;
   	33: //LCD backlight white
   		IF p3B_LcdBacklightWhite_w <> p3B_LcdBacklightWhite_r or bsFaultDataRecive
   		THEN
   	      	vnParameterAdrSend := 59;
   			vnParameterDataSend:= p3B_LcdBacklightWhite_w;
   		END_IF;
   	34: //LCD backlight red
   		IF p3C_LcdBacklightRed_w <> p3C_LcdBacklightRed_r or bsFaultDataRecive
   		THEN
   	      	vnParameterAdrSend := 60;
   			vnParameterDataSend:= p3C_LcdBacklightRed_w;
   		END_IF;
   	35: //Key function enable3: Configuration enable via keyboard
   		IF p3D_KeyFunctionEnable3Config_w <> p3D_KeyFunctionEnable3Config_r or bsFaultDataRecive
   		THEN
   	      	vnParameterAdrSend := 61;
   			vnParameterDataSend:= p3D_KeyFunctionEnable3Config_w;
   		END_IF;
   	36: //Acknowledgement settings
   		IF p3E_AcknowledgementSettings_w <> p3E_AcknowledgementSettings_r or bsFaultDataRecive
   		THEN
   	      	vnParameterAdrSend := 62;
   			vnParameterDataSend:= p3E_AcknowledgementSettings_w;
   		END_IF;
   	37: //Indication factor
   		(*
   		IF p3F_IndicationFactor_w <> p3F_IndicationFactor_r or bsFaultDataRecive
   		THEN
   	      	vnParameterAdrSend := 63;
   			vnParameterDataSend:= p3F_IndicationFactor_w;
   		END_IF;
   		*)
   	38: //Calibration travel
   		IF pA7_ExecuteCalibration_w >= 0 and pA7_ExecuteCalibration_w <= 1
   		THEN
   	      	vnParameterAdrSend := 167;
   			vnParameterDataSend:= pA7_ExecuteCalibration_w;
   		END_IF;
   
   	39: //Freeze actual value
   		IF pAA_FreezeAV_w = 1
   		THEN
   	      	vnParameterAdrSend := 170;
   			vnParameterDataSend:= pAA_FreezeAV_w;
   		END_IF;
   	40: //Response delay
   		IF pD0_ResponseDelay_w <> pD0_ResponseDelay_r or bsFaultDataRecive
   		THEN
   	      	vnParameterAdrSend := 208;
   			vnParameterDataSend:= pD0_ResponseDelay_w;
   		END_IF;
   	41: //Auto-ID assignment
   		IF pD2_AutoIdAssignment_w >= 1 and pD2_AutoIdAssignment_w <= 31
   		THEN
   	      	vnParameterAdrSend := 210;
   			vnParameterDataSend:= pD2_AutoIdAssignment_w;
   		END_IF;
   	42: //Setpoint1
   		IF pFB_SetPoint1_w <> pFB_SetPoint1_r or bsFaultDataRecive
   		THEN
   	      	vnParameterAdrSend := 251;
   			vnParameterDataSend:= pFB_SetPoint1_w;
   		END_IF;
   	43: //S-Befehl
   		IF pA0_SystemCommand_w >= 1 and pA0_SystemCommand_w <= 9 // check, if value is between 1 and 9
   		THEN
   	      	vnParameterAdrSend := 160;
   			vnParameterDataSend:= pA0_SystemCommand_w;
   		END_IF;
   	44:	nCounterWrite := 0;
   	END_CASE;
   end_if;
   
   ///////////////////////////////////////////////////////////////////////////////////////////////
   // Read/Write standard values and three free parameters if parameter read/write inactive
   //
   if (nCounterRead = 0) and (nCounterWrite = 0)
   then
   	if (vnCounterToggle < 1) or (vnCounterToggle > 5)
   	then
   		vnCounterToggle := 1;
   	end_if;
   
   	CASE vnCounterToggle OF
   	1:	//check SetValue and transmit
   		DC_OutputBuffer[0] := 1;
      		vnParameterAdrSend := 255;
   		vnParameterDataSend := nSetValue;
   
   		if ((vnParameterAdrReceive = 255) or (vnParameterAdrReceive > 251)) and DC_InputBuffer[0] = 1
   		then
   			vnCounterToggle := vnCounterToggle + 1;
   		end_if;
   
   	2:	//vnParameterAdrRead1
   		if ((16#00ff and nParameterAdrRead1) < 253) or ((16#00ff and nParameterAdrRead1) = 255)
   		then
   			DC_OutputBuffer[0] := 0;
   			vnParameterAdrSend := nParameterAdrRead1;
   			vnParameterDataSend := 0;
   		else
   			vnCounterToggle := vnCounterToggle + 1;
   		end_if;
   
   		if vnParameterAdrReceive = (16#00ff and nParameterAdrRead1) and DC_InputBuffer[0] = 0
   		then
   			vnCounterToggle := vnCounterToggle + 1;
   		end_if;
   
   	3:	//vnParameterAdrRead2
   		if ((16#00ff and nParameterAdrRead2) < 253) or ((16#00ff and nParameterAdrRead2) = 255)
   		then
   			DC_OutputBuffer[0] := 0;
   			vnParameterAdrSend := nParameterAdrRead2;
   			vnParameterDataSend := 0;
   		else
   			vnCounterToggle := vnCounterToggle + 1;
   		end_if;
   
   		if vnParameterAdrReceive = (16#00ff and nParameterAdrRead2) and DC_InputBuffer[0] = 0
   		then
   			vnCounterToggle := vnCounterToggle + 1;
   		end_if;
   
   	4:	//vnParameterAdrRead3
   		if ((16#00ff and nParameterAdrRead3) < 253)  or ((16#00ff and nParameterAdrRead3) = 255)
   		then
   			DC_OutputBuffer[0] := 0;
   			vnParameterAdrSend := nParameterAdrRead3;
   			vnParameterDataSend := 0;
   		else
   			vnCounterToggle := vnCounterToggle + 1;
   		end_if;
   
   		if vnParameterAdrReceive = (16#00ff and nParameterAdrRead3) and DC_InputBuffer[0] = 0
   		then
   			vnCounterToggle := vnCounterToggle + 1;
   		end_if;
   
   	5:	//read position value
   		if pAA_FreezeAV_w = 0
   		then
   			DC_OutputBuffer[0] := 0;
   			vnParameterAdrSend := 254;
   			vnParameterDataSend := 0;
   		else
   			vnCounterToggle := vnCounterToggle + 1;
   		end_if;
   
   		if (vnParameterAdrReceive = 254) and DC_InputBuffer[0] = 0
   		then
   			vnCounterToggle := vnCounterToggle + 1;
   		end_if;
   	END_CASE;
   else
   	vnCounterToggle := 0;
   end_if;
   
   ///////////////////////////////////////////////////////////////////////////////////////////////
   // Because of Arthmetic overflow
   //
   if vnTrigger >= 127
   then
    vnTrigger := -128;
   end_if;
   vnTrigger := vnTrigger + 1; // ABC Update mode: Change of state on trigger
   
   ///////////////////////////////////////////////////////////////////////////////////////////////
   // Telegram will be completed
   //
   DC_OutputBuffer[1] := nNodeId;
   DC_OutputBuffer[2] := 16#00ff and vnParameterAdrSend;
   DC_OutputBuffer[9] := vnTrigger; // Trigger transmit
   
   ///////////////////////////////////////////////////////////////////////////////////////////////
   ///////////////////////////////////////////////////////////////////////////////////////////////
   
   ///////////////////////////////////////////////////////////////////////////////////////////////
   // Confirmation of Parameter request / Parameter Settings
   //
   IF DC_InputBuffer[1] = nNodeId //Check node address
   THEN
   //	vnParameterAdrReceive := 16#00ff and DC_InputBuffer[2]; //Check command acknowledgment
   	CASE vnParameterAdrReceive OF
   		254: //Position value
   			COP (vnParameterDataReceive,pFE_ActualPosition_r,1);
         		COP (vnParameterDataReceive,nActualValue,1);
   		255: //Setpoint2
   			COP (vnParameterDataReceive,pFF_SetPoint2_r,1);
   		0: //Note address
   			COP (vnParameterDataReceive,p00_NodeAddress_r,1);
   		1: //Baudrate
   			COP (vnParameterDataReceive,p01_Baudrate_r,1);
   		2: //Bus Timeout
   			COP (vnParameterDataReceive,p02_BusTimeout_r,1);
   		3: //Response parameter to a setpoint write access
   			COP (vnParameterDataReceive,p03_ReplyWriteSetPoint_r,1);
   		4: //Keys enable time: Configuration start delay
   			COP (vnParameterDataReceive,p04_EnableKeysTime_r,1);
   		5: //Key function enable1: Calibration enable
   			COP (vnParameterDataReceive,p05_KeyFunctionEnable1Calibrate_r,1);
   		6: //LED flashing
   			COP (vnParameterDataReceive,p06_LedFlashing_r,1);
   		7: //LED3 (green right)
   			COP (vnParameterDataReceive,p07_Led3Green_r,1);
   		8: //LED2 (red left)
   			COP (vnParameterDataReceive,p08_Led2Red_r,1);
   		9: //LED1 (green left)
   			COP (vnParameterDataReceive,p09_Led1Green_r,1);
   		10: //Decimal places
   			COP (vnParameterDataReceive,p0A_DecimalPlaces_r,1);
   		11: //Display divisor (ADI)
   			COP (vnParameterDataReceive,p0B_DisplayDivisor_r,1);
   		12: //Direction indicators (CW, CCW)
   			COP (vnParameterDataReceive,p0C_DirectionIndication_r,1);
   		13: //Display orientation
   			COP (vnParameterDataReceive,p0D_DisplayOrientation_r,1);
   		14: //Configuration programming mode
   			COP (vnParameterDataReceive,p0E_ProgrammingMode_r,1);
   		27: //Counting direction
   			COP (vnParameterDataReceive,p1B_CountingDirection_r,1);
   		28: //Resolution per revolution
   			COP (vnParameterDataReceive,p1C_ResolutionPerRevolution_r,1);
   		30: //Offset value
   			COP (vnParameterDataReceive,p1E_Offset_r,1);
   		31: //Calibration value
   			COP (vnParameterDataReceive,p1F_CalibrationValue_r,1);
   		32: //Target window1 (near field)
   			COP (vnParameterDataReceive,p20_TargetWindow1_r,1);
   		33: //Positioning type (loop type)
   			COP (vnParameterDataReceive,p21_PosType_r,1);
   		34: //Loop length
   			COP (vnParameterDataReceive,p22_LoopLength_r,1);
   		40: //Operating mode
   			COP (vnParameterDataReceive,p28_OperatingMode_r,1);
   		48: //Display in the 2nd row
   			COP (vnParameterDataReceive,p30_Display2Line_r,1);
   		49: //Target window2 (extended)
   			COP (vnParameterDataReceive,p31_TargetWindow2_r,1);
   		50: //Target window2 visualization
   			COP (vnParameterDataReceive,p32_PosWindow2Visual_r,1);
   		51: //Application of the display divisor (ADI application)
   			COP (vnParameterDataReceive,p33_DisplayDivisorUse_r,1);
   		52: //Formation of the differential value
   			COP (vnParameterDataReceive,p34_DifferenceValueCalc_r,1);
   		53: //Key function enable2: Incremental measurement enable
   			COP (vnParameterDataReceive,p35_KeyFunctionEnable2IncrMeas_r,1);
   		57:	//LED4 (red right)
   			COP (vnParameterDataReceive,p39_Led4Red_r,1);
   		58:	//LCD backlight flashing
   			COP (vnParameterDataReceive,p3A_LcdBacklightFlashing_r,1);
   		59:	//LCD backlight white
   			COP (vnParameterDataReceive,p3B_LcdBacklightWhite_r,1);
   		60:	//LCD backlight red
   			COP (vnParameterDataReceive,p3C_LcdBacklightRed_r,1);
   		61: //Key function enable3: Configuration enable via keyboard
   			COP (vnParameterDataReceive,p3D_KeyFunctionEnable3Config_r,1);
   		62:	//Acknowledgement settings
   			COP (vnParameterDataReceive,p3E_AcknowledgementSettings_r,1);
   		63: //Indication factor
   			COP (vnParameterDataReceive,p3F_IndicationFactor_r,1);
   		99: //Battery voltage
   			COP (vnParameterDataReceive,p63_VoltageBattery_r,1);
   		101: //Device identification
   			COP (vnParameterDataReceive,p65_DeviceCode_r,1);
   		103: //Software version
   			COP (vnParameterDataReceive,p67_SoftwareVersion_r,1);
   		128: //Number of errors
   			COP (vnParameterDataReceive,p80_NumberOfErrorsRecorded_r,1);
   		129: //Error01
   			COP (vnParameterDataReceive,p81_Error01_r,1);
   		130: //Error02
   			COP (vnParameterDataReceive,p82_Error02_r,1);
   		131: //Error03
   			COP (vnParameterDataReceive,p83_Error03_r,1);
   		132: //Error04
   			COP (vnParameterDataReceive,p84_Error04_r,1);
   		133: //Error05
   			COP (vnParameterDataReceive,p85_Error05_r,1);
   		134: //Error06
   			COP (vnParameterDataReceive,p86_Error06_r,1);
   		135: //Error07
   			COP (vnParameterDataReceive,p87_Error07_r,1);
   		136: //Error08
   			COP (vnParameterDataReceive,p88_Error08_r,1);
   		137: //Error09
   			COP (vnParameterDataReceive,p89_Error09_r,1);
   		138: //Error10
   			COP (vnParameterDataReceive,p8A_Error10_r,1);
   		150: //Input errors
   			COP (vnParameterDataReceive,p96_InputErrors_r,1);
   		197: //ADC values of the sensor
   			COP (vnParameterDataReceive,pC5_AdcValuesSensor_r,1);
   		207: //Period counter
   			COP (vnParameterDataReceive,pCF_PeriodCounter_r,1);
   		208: //Response delay
   			COP (vnParameterDataReceive,pD0_ResponseDelay_r,1);
   		250: //System Status word
   			COP (vnParameterDataReceive,pFA_SystemStatusword_r,1);
   		251: //Setpoint1
   			COP (vnParameterDataReceive,pFB_SetPoint1_r,1);
   		252: //Differential value
   			COP (vnParameterDataReceive,pFC_DifferentialValue_r,1);
   		END_CASE;
   END_IF;
   
   ///////////////////////////////////////////////////////////////////////////////////////////////
   // handle copy instruction
   //
   
   IF (nCounterCopy > 0)
   THEN
   	p00_NodeAddress_w := p00_NodeAddress_r;
   	p01_Baudrate_w := p01_Baudrate_r;
   	p02_BusTimeout_w := p02_BusTimeout_r;
   	p03_ReplyWriteSetPoint_w := p03_ReplyWriteSetPoint_r;
   	p04_EnableKeysTime_w := p04_EnableKeysTime_r;
   	p05_KeyFunctionEnable1Calibrate_w := p05_KeyFunctionEnable1Calibrate_r;
   	p06_LedFlashing_w := p06_LedFlashing_r;
   	p07_Led3Green_w := p07_Led3Green_r;
   	p08_Led2Red_w := p08_Led2Red_r;
   	p09_Led1Green_w := p09_Led1Green_r;
   	p0A_DecimalPlaces_w := p0A_DecimalPlaces_r;
   	p0B_DisplayDivisor_w := p0B_DisplayDivisor_r;
   	p0C_DirectionIndication_w := p0C_DirectionIndication_r;
   	p0D_DisplayOrientation_w := p0D_DisplayOrientation_r;
   	p0E_ProgrammingMode_w := p0E_ProgrammingMode_r;
   	p1B_CountingDirection_w := p1B_CountingDirection_r;
   	p1C_ResolutionPerRevolution_w := p1C_ResolutionPerRevolution_r;
   	p1E_Offset_w := p1E_Offset_r;
   	p1F_CalibrationValue_w := p1F_CalibrationValue_r;
   	p20_TargetWindow1_w := p20_TargetWindow1_r;
   	p21_PosType_w := p21_PosType_r;
   	p22_LoopLength_w := p22_LoopLength_r;
   	p28_OperatingMode_w := p28_OperatingMode_r;
   	p30_Display2Line_w := p30_Display2Line_r;
   	p31_TargetWindow2_w := p31_TargetWindow2_r;
   	p32_PosWindow2Visual_w := p32_PosWindow2Visual_r;
   	p33_DisplayDivisorUse_w := p33_DisplayDivisorUse_r;
   	p34_DifferenceValueCalc_w := p34_DifferenceValueCalc_r;
   	p35_KeyFunctionEnable2IncrMeas_w := p35_KeyFunctionEnable2IncrMeas_r;
   	p39_Led4Red_w := p39_Led4Red_r;
   	p3A_LcdBacklightFlashing_w := p3A_LcdBacklightFlashing_r;
   	p3B_LcdBacklightWhite_w := p3B_LcdBacklightWhite_r;
   	p3C_LcdBacklightRed_w := p3C_LcdBacklightRed_r;
   	p3D_KeyFunctionEnable3Config_w := p3D_KeyFunctionEnable3Config_r;
   	p3E_AcknowledgementSettings_w := p3E_AcknowledgementSettings_r;
   	p3F_IndicationFactor_w := p3F_IndicationFactor_r;
   	pD0_ResponseDelay_w := pD0_ResponseDelay_r;
   	pFB_SetPoint1_w := pFB_SetPoint1_r;
   	pFF_SetPoint2_w := pFF_SetPoint2_r;
   
   	nCounterCopy := 0;
   END_IF;
   
   ///////////////////////////////////////////////////////////////////////////////////////////////
   // Status word
   //
   bs00_DirectionIndicationCw 					:= DC_InputBuffer[4].0; //direction_display >
   bs01_DirectionIndicationCcw					:= DC_InputBuffer[4].1; //direction_display <
   bs02_ValiditySetpoint1 						:= DC_InputBuffer[4].2; //set_value1_ack
   bs03_TargetWindow2Dynamic					:= DC_InputBuffer[4].3; //targetWindow2_dynamic
   bs04_TargetWindow1Static					:= DC_InputBuffer[4].4; //targetWindow1_static
   bs05_TargetWindow1Dynamic					:= DC_InputBuffer[4].5; //targetWindow1_dynamic
   bs06_Deviation								:= DC_InputBuffer[4].6; //deviation
   bs07_DeviceError 							:= DC_InputBuffer[4].7; //error_ZSW
   bs08_OutputOfPositionValue		 			:= DC_InputBuffer[3].0; //AV_position
   bs09_PositionValueIncrementalMeasurement	:= DC_InputBuffer[3].1; //incremental_measure
   bs10_ValiditySetpoint2          			:= DC_InputBuffer[3].2; //set_value2_ack
   bs11_BatteryStatus 							:= DC_InputBuffer[3].3; //Low_Battery
   bs12_SensorError           					:= DC_InputBuffer[3].4; //Sensor_Error
   bs13_ButtonLeft 							:= DC_InputBuffer[3].5; //button_left
   bs14_ButtonStar 							:= DC_InputBuffer[3].6; //button_star
   bs15_ButtonUp 								:= DC_InputBuffer[3].7; //button_up
   
   ///////////////////////////////////////////////////////////////////////////////////////////////
   // Read and Write cycle completed or inactive
   //
   if nCounterRead = 0 and nCounterWrite = 0 and nCounterCopy = 0
   then
   	bsDone := 1;
   	bsBusy :=0;
   else
   	bsDone :=0;
   	bsBusy := 1;
   end_if;
   
   ///////////////////////////////////////////////////////////////////////////////////////////////
   // Dievice or transmit error occured
   //
   if bsFaultDataRecive or bs07_DeviceError
   then
   	bsGeneralError := 1;
   	bsDone :=0;
   else
   	bsGeneralError := 0;
   end_if;
   
   ///////////////////////////////////////////////////////////////////////////////////////////////
   // parameter data byte swop to output
   //
   swpb (vnParameterDataSend, Reverse, vnDcOutputBufferTemp);
   Cop (vnDcOutputBufferTemp, DC_OutputBuffer[5], 4);					//Data Type Conversion
   
   ///////////////////////////////////////////////////////////////////////////////////////////////
   // Write outputs synchonous
   //
   CPS(DC_OutputBuffer[0],DC_AbcOutputRegister.data[DC_AbcStartByteOut+vnOutputDataOffset],10); //transmit to ABC
END_ROUTINE
END_ADD_ON_INSTRUCTION

ADD_ON_INSTRUCTION SIKO_SN5_COM   (* revision 1.0, vendor SIKO GmbH *)
// Communication
VAR_IN_OUT
   DC_AbcOutRegister : AB:ETHERNET_MODULE_SINT_314Bytes:O:0; {required}
   DC_AbcInRegister : AB:ETHERNET_MODULE_SINT_314Bytes:I:0; {required}
   DC_OutBuffer : SINT[10]; {required}
   DC_InBuffer : SINT[10]; {required}
END_VAR
VAR_INPUT
   nNodeId : SINT := 31; {visible}   // Temporaray Node_address
END_VAR
VAR_OUTPUT
   nActualVal : DINT; {access Read Only, visible}
END_VAR
VAR_INPUT
   nSetVal : DINT; {visible}
END_VAR
VAR_OUTPUT
   nErrActive : SINT; {access Read Only, visible}
   bsComTimeout : BOOL; {access Read Only, visible}
END_VAR
VAR_INPUT
   bc00 : BOOL;
   bc01 : BOOL;
   bc02 : BOOL;
   bc03 : BOOL;
   bc04 : BOOL;
   bc05 : BOOL;
   bc06 : BOOL;
   bc07 : BOOL;
   bc08 : BOOL;
   bc09 : BOOL;
   bc10 : BOOL;
   bc11 : BOOL;
   bc12 : BOOL;
   bc13 : BOOL;
   bc14 : BOOL;
   bc15 : BOOL;
   bcCal : BOOL;
   bcResetFB : BOOL;
   bcSetValRel : BOOL;
   bcUpdMode : BOOL;
   bPara3Write : BOOL;
   DC_StartByteO : INT; {access None}
   DC_StartByteI : INT; {access None}
   nPara1Adr : INT := 16#00fe;
   nPara2Adr : INT := 16#00fe;
   nPara3Adr : INT := 16#00fe;
   nPara3Cmd : SINT;
   nPara3Val : DINT;
END_VAR
VAR_OUTPUT
   bPara1FD : BOOL; {access Read Only}
   bPara2FD : BOOL; {access Read Only}
   bPara3FD : BOOL; {access Read Only}
   bs00 : BOOL; {access Read Only}
   bs01 : BOOL; {access Read Only}
   bs02 : BOOL; {access Read Only}
   bs03 : BOOL; {access Read Only}
   bs04 : BOOL; {access Read Only}
   bs05 : BOOL; {access Read Only}
   bs06 : BOOL; {access Read Only}
   bs07 : BOOL; {access Read Only}
   bs08 : BOOL; {access Read Only}
   bs09 : BOOL; {access Read Only}
   bs10 : BOOL;
   bs11 : BOOL; {access Read Only}
   bs12 : BOOL;
   bs13 : BOOL; {access Read Only}
   bs14 : BOOL; {access Read Only}
   bs15 : BOOL; {access Read Only}
   bsCalExec : BOOL; {access Read Only}
   bsFaultDataRec : BOOL; {access Read Only}
   bsGeneralErr : BOOL; {access Read Only}
   bsUpdBusy : BOOL; {access Read Only}
   bsUpdDone : BOOL; {access Read Only}
   nErrCode1 : SINT; {access Read Only}
   nErrCode2 : SINT; {access Read Only}
   nPara1AdrRec : INT; {access Read Only}
   nPara1ValRec : DINT; {access Read Only}
   nPara2AdrRec : INT; {access Read Only}
   nPara2ValRec : DINT; {access Read Only}
   nPara3AdrRec : INT; {access Read Only}
   nPara3ValRec : DINT; {access Read Only}
   p02_BusTimeout_r : SINT; {access Read Only}
   p8A_Error10_r : SINT; {access Read Only}
   p65_DeviceTyp_r : SINT; {access Read Only}
   p80_ErrQty_r : SINT; {access Read Only}
   p81_Error01_r : SINT; {access Read Only}
   p82_Error02_r : SINT; {access Read Only}
   p83_Error03_r : SINT; {access Read Only}
   p84_Error04_r : SINT; {access Read Only}
   p85_Error05_r : SINT; {access Read Only}
   p86_Error06_r : SINT; {access Read Only}
   p87_Error07_r : SINT; {access Read Only}
   p88_Error08_r : SINT; {access Read Only}
   p89_Error09_r : SINT; {access Read Only}
   vbParaWriteBusy : BOOL; {access None}
   vbUpdActive : BOOL; {access Read Only}
   vnCounterToggle : SINT; {access Read Only}
   vnCounterUpd : SINT; {access Read Only}
END_VAR
VAR
   DC_InputBufferTemp : DINT; {access None}
   DC_OutputBufferTemp : DINT; {access None}
   vbCal : BOOL; {access None}
   vbFDMem1 : BOOL; {access None}
   vbFDMem2 : BOOL; {access None}
   vbFDMem3 : BOOL; {access None}
   vbInitUpd : BOOL; {access None}
   vbOsrCal : BOOL; {access None}
   vbOsrDeviceErr : BOOL; {access None}
   vbOsrParaWrite : BOOL; {access None}
   vbOsrUpdMode : BOOL; {access None}
   vbParaWrite : BOOL; {access None}
   vbUpdMode : BOOL; {access None}
   vnCountDcByte : INT := 4; {access None}
   vnNodeIdBuf : SINT := 31; {access None}
   vnNodeIdMem : SINT; {access None}
   vnParaAdrRec : INT; {access None}
   vnParaAdrSend : INT; {access None}
   vnParaDataRec : DINT; {access None}
   vnParaDataSend : DINT; {access None}
   vnRxTimer : FBD_TIMER; {access None}
   vnTriggerRx : SINT; {access None}
   vnTriggerTx : SINT; {access None}
   vnUpdTime : DINT := 10000; {access None}
   vnUpdTimer : FBD_TIMER; {access None}
END_VAR

ROUTINE Logic   (* structured text *)
   ////////////////////////////////////////////////////////////////////////
   // Version history
   ////////////////////////////////////////////////////////////////////////
   // Date       | Vers. | created              | Author          | Remark
   // dd.mm.yyyy |       | with                 |                 |
   // --------------------------------------------------------------------
   // 06.09.2017 | 0.01  | RSLogix5000 V 20.04  | SIKO GmbH / mk  | alpha
   // 27.10.2017 | 0.02  | RSLogix5000 V 20.04  | SIKO GmbH / mk  | beta
   // 10.10.2018 | 1.00  | RSLogix5000 V 19.01  | SIKO GmbH / mk  | RC
   ////////////////////////////////////////////////////////////////////////
   //
   ///////////////////////////////////////////////////////////////////////////////////////////////
   // Init at first scan
   //
   IF s:fs THEN
       vnCounterUpd := 0;
       vbUpdActive := 0;
       vnCounterToggle := 0;
       vbParaWriteBusy := 0;
       bcResetFB := 0;
   	vbInitUpd := 1;
   
   	FOR vnCountDcByte := 4 TO 313 BY 1 DO				//Delete "DC_AbcOutRegister" at start up
   		DC_AbcOutRegister.Data[vnCountDcByte] := 0;
   	END_FOR;
   
   END_IF;
   
   ///////////////////////////////////////////////////////////////////////////////////////////////
   // Frezze tags for cylic consistency
   //
   
   vnNodeIdBuf := nNodeId;
   
   ///////////////////////////////////////////////////////////////////////////////////////////////
   // Calculation of buffer area accordingly to node ID
   //
   if (vnNodeIdBuf > 0 AND vnNodeIdBuf < 32)
   THEN
   	DC_StartByteI := (vnNodeIdBuf * 10) - 6;
   	DC_StartByteO := DC_StartByteI;
   ELSE
   	DC_StartByteI := 4;
   	DC_StartByteO := DC_StartByteI;
   END_IF;
   
   
   ///////////////////////////////////////////////////////////////////////////////////////////////
   // Read inputs synchonous
   //
   CPS(DC_AbcInRegister.data[DC_StartByteI] , DC_InBuffer[0],10); // read from ABC
   
   ///////////////////////////////////////////////////////////////////////////////////////////////
   // Input byte swop to parameter data and format transfer vnParameterAdrReceive
   //
   cop (DC_InBuffer[5], DC_InputBufferTemp, 1);					//Data Type Conversion
   swpb (DC_InputBufferTemp, Reverse, vnParaDataRec);
   
   vnParaAdrRec := 16#00ff and DC_InBuffer[2];
   
   ///////////////////////////////////////////////////////////////////////////////////////////////
   // Status word
   //
   bs00 := DC_InBuffer[4].0;
   bs01 := DC_InBuffer[4].1;
   bs02 := DC_InBuffer[4].2;
   bs03 := DC_InBuffer[4].3;
   bs04 := DC_InBuffer[4].4;
   bs05 := DC_InBuffer[4].5;
   bs06 := DC_InBuffer[4].6;
   bs07 := DC_InBuffer[4].7;
   bs08 := DC_InBuffer[3].0;
   bs09 := DC_InBuffer[3].1;
   bs10 := DC_InBuffer[3].2;
   bs11 := DC_InBuffer[3].3;
   bs12 := DC_InBuffer[3].4;
   bs13 := DC_InBuffer[3].5;
   bs14 := DC_InBuffer[3].6;
   bs15 := DC_InBuffer[3].7;
   
   ///////////////////////////////////////////////////////////////////////////////////////////////
   // Increase #vnCounterUpd
   //
   IF (vnParaAdrSend = vnParaAdrRec)
   	OR ((vnParaAdrSend = 16#03) AND (vnParaAdrRec = 16#FD)) 														// Error writing parameter 03 while axis is moving
   	OR ((vnParaAdrSend = 16#A0) AND (vnParaAdrRec = 16#FD)) 														// Error writing parameter A0 while axis is moving
   THEN
       IF ((vnCounterUpd > 0) AND (vnCounterUpd < 3)) OR ((vnCounterUpd > 14) AND (vnCounterUpd < 16))					// Check general information
       THEN
   		vnCounterUpd := vnCounterUpd + 1;
       ELSIF ((vnCounterUpd >= 3) AND (vnCounterUpd <= 14))  AND ((p65_DeviceTyp_r <> 1) AND (p65_DeviceTyp_r <> 4)) 	// Check if error buffer is present
       	AND (vnCounterUpd < (p80_ErrQty_r + 4))																		// Read control for filled error buffer
       THEN
           vnCounterUpd := vnCounterUpd + 1;
   	ELSE
           vnCounterUpd := 0;
           vbUpdActive := 0;
       END_IF;
   END_IF;
   
   ///////////////////////////////////////////////////////////////////////////////////////////////
   // Calibration
   //
   vbOsrCal := bcCal AND NOT (vbCal);
   vbCal := bcCal;
   
   IF vbOsrCal AND NOT vbUpdActive
   THEN
       vbUpdActive := 1;
       vnCounterUpd := 15;
   END_IF;
   
   IF bsCalExec AND NOT bcCal
   THEN
   	bsCalExec := 0;
   END_IF;
   
   ///////////////////////////////////////////////////////////////////////////////////////////////
   // Data update
   //
   vbOsrUpdMode := bcUpdMode AND NOT (vbUpdMode);
   vbUpdMode := bcUpdMode;
   
   IF NOT bcUpdMode THEN
   vnUpdTimer.Pre :=  vnUpdTime;
   vnUpdTimer.Reset := vnCounterUpd <> 0;
   vnUpdTimer.TimerEnable := vnCounterUpd = 0;
   RTOR(vnUpdTimer);
   END_IF;
   
   IF vnUpdTimer.Dn
   THEN
       vnUpdTime := vnUpdTime * 2;
   END_IF;
   
   IF bs07 OR vbOsrUpdMode
   THEN
       vnUpdTime := 10000;
   ELSIF (vnUpdTime > 10000)
   THEN
       vnUpdTime := 300000;
   END_IF;
   
   IF  ((bs07 AND NOT (vbOsrDeviceErr)) OR vbOsrUpdMode OR vbInitUpd OR vnUpdTimer.DN)      		// One Condition required
       AND ((nPara3Cmd = 16#00) OR (nPara3Cmd = 16#01))                                   		  // Conditions status required
       AND NOT (vbUpdActive)                                                                	  // Condition not allowed
   THEN
       vbOsrDeviceErr := 1;
       vbUpdActive := 1;
       vnCounterUpd := 1;
   END_IF;
   
   IF NOT bs07
   THEN
       vbOsrDeviceErr := 0;
   END_IF;
   
   IF vnNodeIdBuf <> vnNodeIdMem
   THEN
       vbInitUpd := 1;
       vnNodeIdMem := vnNodeIdBuf;
   
   	FOR vnCountDcByte := 4 TO 313 BY 1 DO			//Delete "DC_AbcOutRegister" if ID change
   		DC_AbcOutRegister.Data[vnCountDcByte] := 0;
   	END_FOR;
   
   ELSE
       vbInitUpd := 0;
   END_IF;
   
   ///////////////////////////////////////////////////////////////////////////////////////////////
   // Data update request
   //
   IF vnCounterUpd > 0
   THEN
       CASE vnCounterUpd OF
           1: //0x65 Device identification
               DC_OutBuffer[0] := 0;
   			vnParaAdrSend := 101;
   			vnParaDataSend := 0;
               vnTriggerTx := vnTriggerTx + 1;
           2: // 0x02 Bus timeout
   			DC_OutBuffer[0] := 0;
               vnParaAdrSend := 2;
   			vnParaDataSend := 0;
               vnTriggerTx := vnTriggerTx + 1;
   		3: // 0x03 Reply parameter to write setpoint command
   			DC_OutBuffer[0] := 1;
               vnParaAdrSend := 3;
   			vnParaDataSend := 0;
   			vnParaDataSend := 1;
               vnTriggerTx := vnTriggerTx + 1;
           4: //0x80 Number of errors
   			DC_OutBuffer[0] := 0;
               vnParaAdrSend := 128;
   			vnParaDataSend := 0;
               vnTriggerTx := vnTriggerTx + 1;
           5: //0x81 Error 01
   			DC_OutBuffer[0] := 0;
               vnParaAdrSend := 129;
   			vnParaDataSend := 0;
               vnTriggerTx := vnTriggerTx + 1;
           6: //0x82 Error 02
   			DC_OutBuffer[0] := 0;
               vnParaAdrSend := 130;
   			vnParaDataSend := 0;
               vnTriggerTx := vnTriggerTx + 1;
           7: //0x83 Error 03
   			DC_OutBuffer[0] := 0;
               vnParaAdrSend := 131;
   			vnParaDataSend := 0;
               vnTriggerTx := vnTriggerTx + 1;
           8: //0x84 Error 04
   			DC_OutBuffer[0] := 0;
               vnParaAdrSend := 132;
   			vnParaDataSend := 0;
               vnTriggerTx := vnTriggerTx + 1;
           9: //0x85 Error 05
   			DC_OutBuffer[0] := 0;
               vnParaAdrSend := 133;
   			vnParaDataSend := 0;
               vnTriggerTx := vnTriggerTx + 1;
           10: //0x86 Error 06
   			DC_OutBuffer[0] := 0;
               vnParaAdrSend := 134;
   			vnParaDataSend := 0;
               vnTriggerTx := vnTriggerTx + 1;
           11: //0x87 Error 07
   			DC_OutBuffer[0] := 0;
               vnParaAdrSend := 135;
   			vnParaDataSend := 0;
               vnTriggerTx := vnTriggerTx + 1;
           12: //0x88 Error 08
   			DC_OutBuffer[0] := 0;
               vnParaAdrSend := 136;
   			vnParaDataSend := 0;
               vnTriggerTx := vnTriggerTx + 1;
           13: //0x89 Error 09
   			DC_OutBuffer[0] := 0;
               vnParaAdrSend := 137;
   			vnParaDataSend := 0;
               vnTriggerTx := vnTriggerTx + 1;
           14: //0x8A Error 10
   			DC_OutBuffer[0] := 0;
               vnParaAdrSend := 138;
   			vnParaDataSend := 0;
               vnTriggerTx := vnTriggerTx + 1;
   		15: //0xA0 S-Command, Execute Calibration
   			DC_OutBuffer[0] := 1;
               vnParaAdrSend := 160;
   			vnParaDataSend := 7;
               vnTriggerTx := vnTriggerTx + 1;
       END_CASE;
   END_IF;
   
   ///////////////////////////////////////////////////////////////////////////////////////////////
   // Confirmation of Data update request
   //
   IF (DC_InBuffer[1] = vnNodeIdBuf) //Check node address
   THEN
       CASE vnParaAdrRec OF
           101: //Device identification
               p65_DeviceTyp_r := vnParaDataRec;
           002: // Bus timeout
               p02_BusTimeout_r := vnParaDataRec;
           128: //Number of errors
               p80_ErrQty_r := vnParaDataRec;
   			IF NOT bs07 THEN
   			p81_Error01_r := 0;
   			p82_Error02_r := 0;
   			p83_Error03_r := 0;
   			p84_Error04_r := 0;
   			p85_Error05_r := 0;
   			p86_Error06_r := 0;
   			p87_Error07_r := 0;
   			p88_Error08_r := 0;
   			p89_Error09_r := 0;
   			p8A_Error10_r := 0;
   			END_IF;
           129: //Error01
               p81_Error01_r := vnParaDataRec;
           130: //Error02
               p82_Error02_r := vnParaDataRec;
           131: //Error03
               p83_Error03_r := vnParaDataRec;
           132: //Error04
               p84_Error04_r := vnParaDataRec;
           133: //Error05
               p85_Error05_r := vnParaDataRec;
           134: //Error06
               p86_Error06_r := vnParaDataRec;
           135: //Error07
               p87_Error07_r := vnParaDataRec;
           136: //Error08
               p88_Error08_r := vnParaDataRec;
           137: //Error09
               p89_Error09_r := vnParaDataRec;
           138: //Error10
               p8A_Error10_r := vnParaDataRec;
   		160: // Calibration executed
   			if (vnParaDataRec = 7)
   			THEN
   				bsCalExec := 1;
   			END_IF;
       END_CASE;
   END_IF;
   
   ///////////////////////////////////////////////////////////////////////////////////////////////
   // Error output
   //
   IF NOT bs07 THEN
   	nErrActive := 0;
   END_IF;
   
   IF bs07 AND NOT vbUpdActive
   THEN
   	CASE p80_ErrQty_r OF
   	    0: // NO Error
   	        nErrActive := 0;
   	    1: // Error Nummber 1
   	        nErrActive := p81_Error01_r;
   	    2: // Error Nummber 2
   	        nErrActive := p82_Error02_r;
   	    3: // Error Nummber 3
   	        nErrActive := p83_Error03_r;
   	    4: // Error Nummber 4
   	        nErrActive := p84_Error04_r;
   	    5: // Error Nummber 5
   	        nErrActive := p85_Error05_r;
   	    6: // Error Nummber 6
   	        nErrActive := p86_Error06_r;
   	    7: // Error Nummber 7
   	        nErrActive := p87_Error07_r;
   	    8: // Error Nummber 8
   	        nErrActive := p88_Error08_r;
   	    9: // Error Nummber 9
   	        nErrActive := p89_Error09_r;
   	    10: // Error Nummber 10
   	        nErrActive := p8A_Error10_r;
   	END_CASE;
   END_IF;
   
   ///////////////////////////////////////////////////////////////////////////////////////////////
   // Data update cycle completed or inactive
   //
   IF vnCounterUpd = 0
   THEN
       bsUpdDone := 1;
       bsUpdBusy := 0;
   ELSE
       bsUpdDone := 0;
       bsUpdBusy := 1;
   END_IF;
   
   ///////////////////////////////////////////////////////////////////////////////////////////////
   // Read/Write standard values and three free parameters
   // if (Data update OR Block segmented communication) inactive
   //
   IF (vnCounterToggle < 1) OR (vnCounterToggle > 6)
   THEN
       vnCounterToggle := 1;
   END_IF;
   
   IF NOT vbUpdActive
   THEN
       //Cyclic communication aktiv
       IF (nPara3Cmd = 16#00 OR nPara3Cmd = 16#01)
       THEN
           CASE vnCounterToggle OF
   		    1:  //Transmit SetValue
                   //Init
                   DC_OutBuffer[0] := 1;
                   vnParaAdrSend := 255;
                   // Motion profile
                   IF bcSetValRel THEN
                       vnParaDataSend := nSetVal + nActualVal;
                   ELSE
                       vnParaDataSend := nSetVal;
                   END_IF;
   
                   //Transmit ACK?
                   IF (vnParaAdrRec = 254) AND (DC_InBuffer[0] = 1) AND (DC_InBuffer[9] <> vnTriggerRx) //#vnParameterAdrReceive in relation to parameter "03h"
                   THEN //Output and next request
   					nActualVal := vnParaDataRec;
                       vnCounterToggle := vnCounterToggle + 2;
   				ELSIF (vnParaAdrRec <> 254) AND (DC_InBuffer[0] = 1) AND (DC_InBuffer[9] <> vnTriggerRx) THEN
   				  vnCounterToggle := vnCounterToggle + 1;
                   ELSE //Repeat transmit
                       vnTriggerTx := vnTriggerTx + 1;
                   END_IF;
   
               2:  //Inquiry actuel position value
                   //Init
                   DC_OutBuffer[0] := 0;
                   vnParaAdrSend := 254;
                   vnParaDataSend := 0;
   
                   //Inquiry ACK?
                   IF (vnParaAdrRec = 254) AND (DC_InBuffer[0] = 0)
                   THEN //Output and next request
   					nActualVal := vnParaDataRec;
                       vnCounterToggle := vnCounterToggle + 1;
                   ELSE //Repeat request
                       vnTriggerTx := vnTriggerTx + 1;
                   END_IF;
   
   			3:  //Next request, check for active free parameter
                       IF nPara1Adr < 253
   					THEN
                           vnCounterToggle := vnCounterToggle + 1;
                       ELSIF nPara2Adr < 253 THEN
                           nPara1AdrRec := 0;
                           nPara1ValRec := 0;
                           vnCounterToggle := vnCounterToggle + 2;
                       ELSIF nPara3Adr < 253 THEN
                           nPara1AdrRec := 0;
                           nPara1ValRec := 0;
                           nPara2AdrRec := 0;
                           nPara2ValRec := 0;
                           vnCounterToggle := vnCounterToggle + 3;
                       ELSE
                           nPara1AdrRec := 0;
                           nPara1ValRec := 0;
                           nPara2AdrRec := 0;
                           nPara2ValRec := 0;
                           nPara3AdrRec := 0;
                           nPara3ValRec := 0;
                           vnCounterToggle := vnCounterToggle + 4;
                       END_IF;
   
   		    4:  //Inquiry free Parameter 1
                   //Check if free Parameter 1 address is lower then "253" (16#00FD) and bigger "-1" (16#FFFF)
                   IF (nPara1Adr < 253) AND (nPara1Adr >= 0)
                   THEN
                       //Init
                       DC_OutBuffer[0] := 0;
                       vnParaAdrSend := nPara1Adr;
                       vnParaDataSend := 0;
   
                       //Inquiry ACK?
                       IF (vnParaAdrRec = nPara1Adr) AND (DC_InBuffer[0] = 0)
                       THEN //Output, reset chanel error and next request
                           nPara1AdrRec := vnParaAdrRec;
                           nPara1ValRec := vnParaDataRec;
                           vbFDMem1 := 0;
                           nErrCode1 := 0;
                           nErrCode2 := 0;
                           vnCounterToggle := vnCounterToggle + 1;
                       ELSE //Repeat request
                           vnTriggerTx := vnTriggerTx + 1;
                       END_IF;
   
                       //Check for FD-Telegram
                       IF (vnParaAdrRec = 253) AND (DC_InBuffer[9] <> vnTriggerRx)
                       THEN //Output, set chanel error and next request
                           nPara1AdrRec := vnParaAdrRec;
                           nPara1ValRec := vnParaDataRec;
                           vbFDMem1 := 1;
                           nErrCode1 := DC_InBuffer[8];
                           nErrCode2 := DC_InBuffer[7];
                           vnCounterToggle := vnCounterToggle + 1;
                       END_IF;
                   ELSE //Free Parameter 1 address limit overrun next request
   				    nPara1AdrRec := 0;
                       nPara1ValRec := 0;
                       vnCounterToggle := vnCounterToggle + 1;
                   END_IF;
   
   			5:  //Inquiry free Parameter 2
                   //Check if free Parameter 2 address is lower then "253" (16#00FD) and bigger "-1" (16#FFFF)
                   IF (nPara2Adr < 253) AND (nPara2Adr >= 0)
                   THEN
                       //Init
                       DC_OutBuffer[0] := 0;
                       vnParaAdrSend := nPara2Adr;
                       vnParaDataSend := 0;
   
                       //Inquiry ACK?
                       IF (vnParaAdrRec = nPara2Adr) AND (DC_InBuffer[0] = 0)
                       THEN //Output, reset chanel error and next request
                           nPara2AdrRec := vnParaAdrRec;
                           nPara2ValRec := vnParaDataRec;
                           vbFDMem2 := 0;
                           nErrCode1 := 0;
                           nErrCode2 := 0;
                           vnCounterToggle := vnCounterToggle + 1;
                       ELSE //Repeat request
                           vnTriggerTx := vnTriggerTx + 1;
                       END_IF;
   
                       //Check for FD-Telegram
                       IF (vnParaAdrRec = 253) AND (DC_InBuffer[9] <> vnTriggerRx)
                       THEN //Output, set chanel error and next request
                           nPara2AdrRec := vnParaAdrRec;
                           nPara2ValRec := vnParaDataRec;
                           vbFDMem2 := 1;
                           nErrCode1 := DC_InBuffer[8];
                           nErrCode2 := DC_InBuffer[7];
                           vnCounterToggle := vnCounterToggle + 1;
                       END_IF;
                   ELSE //Free Parameter 2 address limit overrun next request
   					nPara2AdrRec := 0;
                       nPara2ValRec := 0;
                       vnCounterToggle := vnCounterToggle + 1;
                   END_IF;
   
               6:  //Inquiry and transmit free Parameter 3
                   //Check if free Parameter 3 address is lower then "253" (16#00FD) and bigger "-1" (16#FFFF)
                   IF (nPara3Adr < 253) AND (nPara3Adr >= 0)
                   THEN
   
                       //Build positive edge #vbParaWriteStart3
                       vbOsrParaWrite := bPara3Write AND NOT vbParaWrite;
                       vbParaWrite := bPara3Write;
   
                       //Set write cycle aktiv
                       IF vbOsrParaWrite
                       THEN
                           vbParaWriteBusy := 1;
                       END_IF;
   
                       //Transmit write Parameter
                       IF vbParaWriteBusy
                       THEN
                           DC_OutBuffer[0] := nPara3Cmd;
                           vnParaAdrSend := nPara3Adr;
                           vnParaDataSend := nPara3Val;
                       ELSE //Inquiry free Parameter 3
                           DC_OutBuffer[0] := 0;
                           vnParaAdrSend := nPara3Adr;
                           //Inquiry addresse
                           IF nPara3Adr <> 150 THEN
                               vnParaDataSend := 0;
                           ELSE //Inquiry addresse 150 with subindex
                               DC_OutBuffer[0] := 0;
                               vnParaDataSend := nPara3Val;
                           END_IF;
                       END_IF;
   
                       //Transmit or inquiry ACK?
                       IF vnParaAdrRec = nPara3Adr
                       THEN //Output, reset chanel error and next request
                           nPara3AdrRec := vnParaAdrRec;
                           nPara3ValRec := vnParaDataRec;
                           vbFDMem3 := 0;
                           nErrCode1 := 0;
                           nErrCode2 := 0;
                           vbParaWriteBusy := 0;
                           vnCounterToggle := vnCounterToggle + 1;
                       ELSE //Repeat request
                           vnTriggerTx := vnTriggerTx + 1;
                       END_IF;
   
                       //Check for FD-Telegram
                       IF (vnParaAdrRec = 253) AND (DC_InBuffer[9] <> vnTriggerRx)
                       THEN //Output, set chanel error and next request
                           nPara3AdrRec := vnParaAdrRec;
                           nPara3ValRec := vnParaDataRec;
                           vbFDMem3 := 1;
                           nErrCode1 := DC_InBuffer[8];
                           nErrCode2 := DC_InBuffer[7];
                           vnCounterToggle := vnCounterToggle + 1;
                       END_IF;
                   ELSE //Free Parameter 3 address limit overrun next request
   					nPara3AdrRec := 0;
                       nPara3ValRec := 0;
                       vnCounterToggle := vnCounterToggle + 1;
                   END_IF;
   		END_Case;
   
   		ELSE //Block segmented communication aktiv
           //Init
           DC_OutBuffer[0] := nPara3Cmd;
           vnParaAdrSend := nPara3Adr;
           vnParaDataSend := nPara3Val;
   
           //Build positive edge #vbParaWriteStart3
           vbOsrParaWrite := bPara3Write AND NOT vbParaWrite;
           vbParaWrite := bPara3Write;
   
           //Transmit a new telegram
           IF vbOsrParaWrite
           THEN
               vbParaWriteBusy := 1;
               vnTriggerTx := vnTriggerTx + 1;
           END_IF;
   
           //Transmit ACK?
           IF (vnParaAdrRec = nPara3Adr) AND (nPara3Cmd = DC_InBuffer[0])
           THEN //Output and reset chanel error
               nPara3AdrRec := vnParaAdrRec;
               nPara3ValRec := vnParaDataRec;
               vbFDMem3  := 0;
               nErrCode1 := 0;
               nErrCode2 := 0;
   			vbParaWriteBusy := 0;
           END_IF;
   
           //Check for FD-Telegram
           IF (vnParaAdrRec = 253) AND (DC_InBuffer[9] <> vnTriggerRx)
           THEN //Output and set chanel error
               nPara3AdrRec := vnParaAdrRec;
               nPara3ValRec := vnParaDataRec;
               vbFDMem3 := 1;
               nErrCode1 := DC_InBuffer[8];
               nErrCode2 := DC_InBuffer[7];
           END_IF;
       END_IF;
   END_IF;
   
   ///////////////////////////////////////////////////////////////////////////////////////////////
   //Because of Arthmetic overflow
   //
   if vnTriggerTx >= 127
   then
    vnTriggerTx := -128;
   end_if;
   
   ///////////////////////////////////////////////////////////////////////////////////////////////
   //FD-Telegram received, set output
   //
   bPara1FD := vbFDMem1;
   bPara2FD := vbFDMem2;
   bPara3FD := vbFDMem3;
   
   ///////////////////////////////////////////////////////////////////////////////////////////////
   // Dievice or transmit error occured
   //
   IF bPara1FD OR bPara2FD OR bPara3FD
   THEN
       bsFaultDataRec := 1;
   ELSE
       bsFaultDataRec := 0;
   END_IF;
   
   IF bsFaultDataRec OR bs07 OR bsComTimeout
   THEN
       bsGeneralErr := 1;
   ELSE
       bsGeneralErr := 0;
   END_IF;
   
   ///////////////////////////////////////////////////////////////////////////////////////////////
   // New telegram arrived in time
   //
   IF (p02_BusTimeout_r = 0)
   THEN
       p02_BusTimeout_r := 100;
   END_IF;
   
   vnRxTimer.Pre := (p02_BusTimeout_r * 100) + 500;							// Span 500 - 2500 ms, equal 0,5 - 2,5ss
   vnRxTimer.Reset := vnTriggerRx <> DC_InBuffer[9];
   vnRxTimer.TimerEnable := vnTriggerRx = DC_InBuffer[9];
   RTOR(vnRxTimer);
   bsComTimeout := vnRxTimer.DN;
   
   vnTriggerRx := DC_InBuffer[9]; // #vnTriggerRx update
   
   ///////////////////////////////////////////////////////////////////////////////////////////////
   // Reset counter
   //
   IF bcResetFB
   THEN
       vnCounterUpd := 0;
       vbUpdActive := 0;
       vnCounterToggle := 0;
       vbParaWriteBusy := 0;
       bcResetFB := 0;
   END_IF;
   
   ///////////////////////////////////////////////////////////////////////////////////////////////
   // Combine Control word / bits
   //
   DC_OutBuffer[4].0 := bc00;
   DC_OutBuffer[4].1 := bc01;
   DC_OutBuffer[4].2 := bc02;
   DC_OutBuffer[4].3 := bc03;
   DC_OutBuffer[4].4 := bc04;
   DC_OutBuffer[4].5 := bc05;
   DC_OutBuffer[4].6 := bc06;
   DC_OutBuffer[4].7 := bc07;
   DC_OutBuffer[3].0 := bc08;
   DC_OutBuffer[3].1 := bc09;
   DC_OutBuffer[3].2 := bc10;
   DC_OutBuffer[3].3 := bc11;
   DC_OutBuffer[3].4 := bc12;
   DC_OutBuffer[3].5 := bc13;
   DC_OutBuffer[3].6 := bc14;
   DC_OutBuffer[3].7 := bc15;
   
   
   ///////////////////////////////////////////////////////////////////////////////////////////////
   // parameter data byte swop to output
   //
   swpb (vnParaDataSend, Reverse, DC_OutputBufferTemp);
   Cop (DC_OutputBufferTemp, DC_OutBuffer[5], 4);					//Data Type Conversion
   
   ///////////////////////////////////////////////////////////////////////////////////////////////
   // Telegram will be completed
   //
   DC_OutBuffer[1] := vnNodeIdBuf;
   DC_OutBuffer[2] := 16#00ff and vnParaAdrSend;
   DC_OutBuffer[9] := vnTriggerTx; // Trigger transmit
   
   ///////////////////////////////////////////////////////////////////////////////////////////////
   // Write outputs synchonous
   //
   CPS(DC_OutBuffer[0],DC_AbcOutRegister.data[DC_StartByteO],10); //transmit to ABC
   
   
   
   
   
END_ROUTINE
END_ADD_ON_INSTRUCTION

ADD_ON_INSTRUCTION SIKO_SN5_PRM   (* revision 1.0, vendor SIKO GmbH *)
// Parameter Access
VAR_IN_OUT
   DC_Com : SIKO_SN5_COM; {required}
END_VAR
VAR_INPUT
   nPara1Adr : SINT := 16#fe; {visible}
   nPara2Adr : SINT := 16#fe; {visible}
   nPara3Adr : SINT := 16#fe; {visible}
   nPara3Cmd : SINT; {visible}
   nPara3Val : DINT; {visible}
   bPara3Write : BOOL; {visible}
END_VAR
VAR_OUTPUT
   nPara1AdrRec : SINT; {access Read Only, visible}
   nPara1ValRec : DINT; {access Read Only, visible}
   nPara2AdrRec : SINT; {access Read Only, visible}
   nPara2ValRec : DINT; {access Read Only, visible}
   nPara3AdrRec : SINT; {access Read Only, visible}
   nPara3ValRec : DINT; {access Read Only, visible}
   bPara1FD : BOOL; {access Read Only, visible}
   bPara2FD : BOOL; {access Read Only, visible}
   bPara3FD : BOOL; {access Read Only, visible}
   bsFaultDataRec : BOOL; {access Read Only, visible}
   nErrCode1 : SINT; {access Read Only, visible}
   nErrCode2 : SINT; {access Read Only, visible}
END_VAR

ROUTINE Logic   (* structured text *)
   ////////////////////////////////////////////////////////////////////////
   // Version history
   ////////////////////////////////////////////////////////////////////////
   // Date       | Vers. | created              | Author          | Remark
   // dd.mm.yyyy |       | with                 |                 |
   // --------------------------------------------------------------------
   // 10.10.2018 | 0.01  | RSLogix5000 V 19.01  | SIKO GmbH / MK  | alpha
   ////////////////////////////////////////////////////////////////////////
   //
   ///////////////////////////////////////////////////////////////////////////////////////////////
   // SN5 Parameter Access
   //
   DC_Com.nPara1Adr 	:= 16#00ff AND nPara1Adr;
   DC_Com.nPara2Adr 	:= 16#00ff AND nPara2Adr;
   DC_Com.nPara3Adr 	:= 16#00ff AND nPara3Adr;
   DC_Com.nPara3Cmd 	:= 16#00ff AND nPara3Cmd;
   DC_Com.nPara3Val 	:= 16#00ff AND nPara3Val;
   DC_Com.bPara3Write := bPara3Write;
   
   nPara1AdrRec  	:= 16#00ff AND DC_Com.nPara1AdrRec;
   nPara2AdrRec 	:= 16#00ff AND DC_Com.nPara2AdrRec;
   nPara3AdrRec 	:= 16#00ff AND DC_Com.nPara3AdrRec;
   nPara1ValRec 	:= DC_Com.nPara1ValRec;
   nPara2ValRec 	:= DC_Com.nPara2ValRec;
   nPara3ValRec 	:= DC_Com.nPara3ValRec;
   bPara1FD 		:= DC_Com.bPara1FD;
   bPara2FD 		:= DC_Com.bPara2FD;
   bPara3FD 		:= DC_Com.bPara3FD;
   bsFaultDataRec  := DC_Com.bsFaultDataRec;
   nErrCode1 		:= DC_Com.nErrCode1;
   nErrCode2 		:= DC_Com.nErrCode2;
   
   
END_ROUTINE
END_ADD_ON_INSTRUCTION

VAR_GLOBAL   (* controller tags *)
   Drive1 : SIKO_SN5_COM := (nNodeId := 5, nPara1Adr := 16#00fe, nPara2Adr := 16#00fe, nPara3Adr := 16#00fe);
   Drive1_CSW : SIKO_AG05_CSW_POS;
   Drive1_DC_In : SINT[10];
   Drive1_DC_Out : SINT[10];
   Drive1_PRM : SIKO_SN5_PRM := (nPara1Adr := 16#fe, nPara2Adr := 16#fe, nPara3Adr := 16#fe);
   Position1 : SIKO_AP10 := (nNodeId := 10, p00_NodeAddress_w := 31, p01_Baudrate_w := 1, p02_BusTimeout_w := 20, p04_EnableKeysTime_w := 5, p05_KeyFunctionEnable1Calibrate_w := 1, p07_Led3Green_w := 1, p08_Led2Red_w := 1, p09_Led1Green_w := 1, p0C_DirectionIndication_w := 1, p1C_ResolutionPerRevolution_w := 880, p30_Display2Line_w := 1, p35_KeyFunctionEnable2IncrMeas_w := 1, p39_Led4Red_w := 1, p3B_LcdBacklightWhite_w := 1, p3C_LcdBacklightRed_w := 1, p3D_KeyFunctionEnable3Config_w := 1);
   Position1_CW : SINT[10];
   Position1_SW : SINT[10];
   Test : DINT;
END_VAR

PROGRAM MainProgram   (* main routine MainRoutine *)

ROUTINE MainRoutine   (* ladder *)
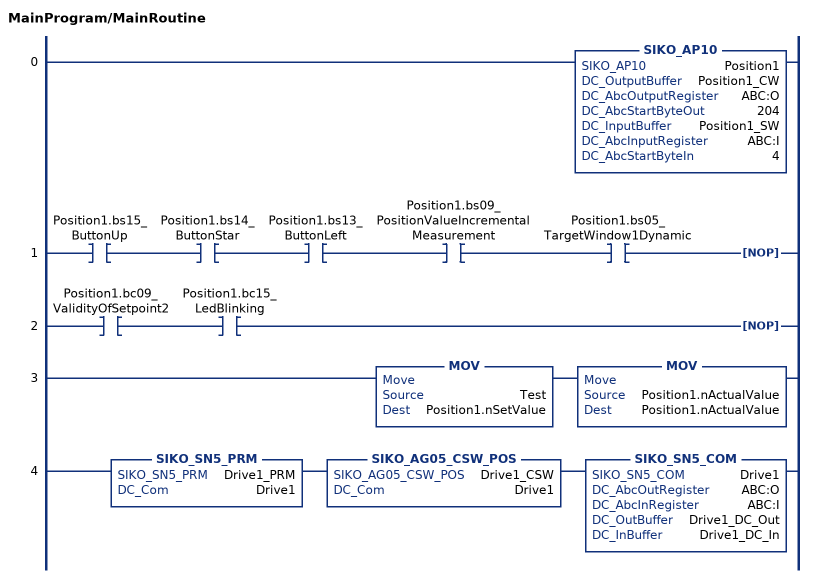
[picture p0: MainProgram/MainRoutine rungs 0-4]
   0: SIKO_AP10(Position1,Position1_CW,ABC:O,204,Position1_SW,ABC:I,4);
   1: XIC(Position1.bs15_ButtonUp)XIC(Position1.bs14_ButtonStar)XIC(Position1.bs13_ButtonLeft)XIC(Position1.bs09_PositionValueIncrementalMeasurement)XIC(Position1.bs05_TargetWindow1Dynamic)NOP();
   2: XIC(Position1.bc09_ValidityOfSetpoint2)XIC(Position1.bc15_LedBlinking)NOP();
   3: MOV(Test,Position1.nSetValue)MOV(Position1.nActualValue,Position1.nActualValue);
   4: SIKO_SN5_PRM(Drive1_PRM,Drive1)SIKO_AG05_CSW_POS(Drive1_CSW,Drive1)SIKO_SN5_COM(Drive1,ABC:O,ABC:I,Drive1_DC_Out,Drive1_DC_In);
END_ROUTINE
END_PROGRAM
